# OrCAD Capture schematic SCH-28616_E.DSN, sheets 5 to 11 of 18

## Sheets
5 M-06 Audio: size C
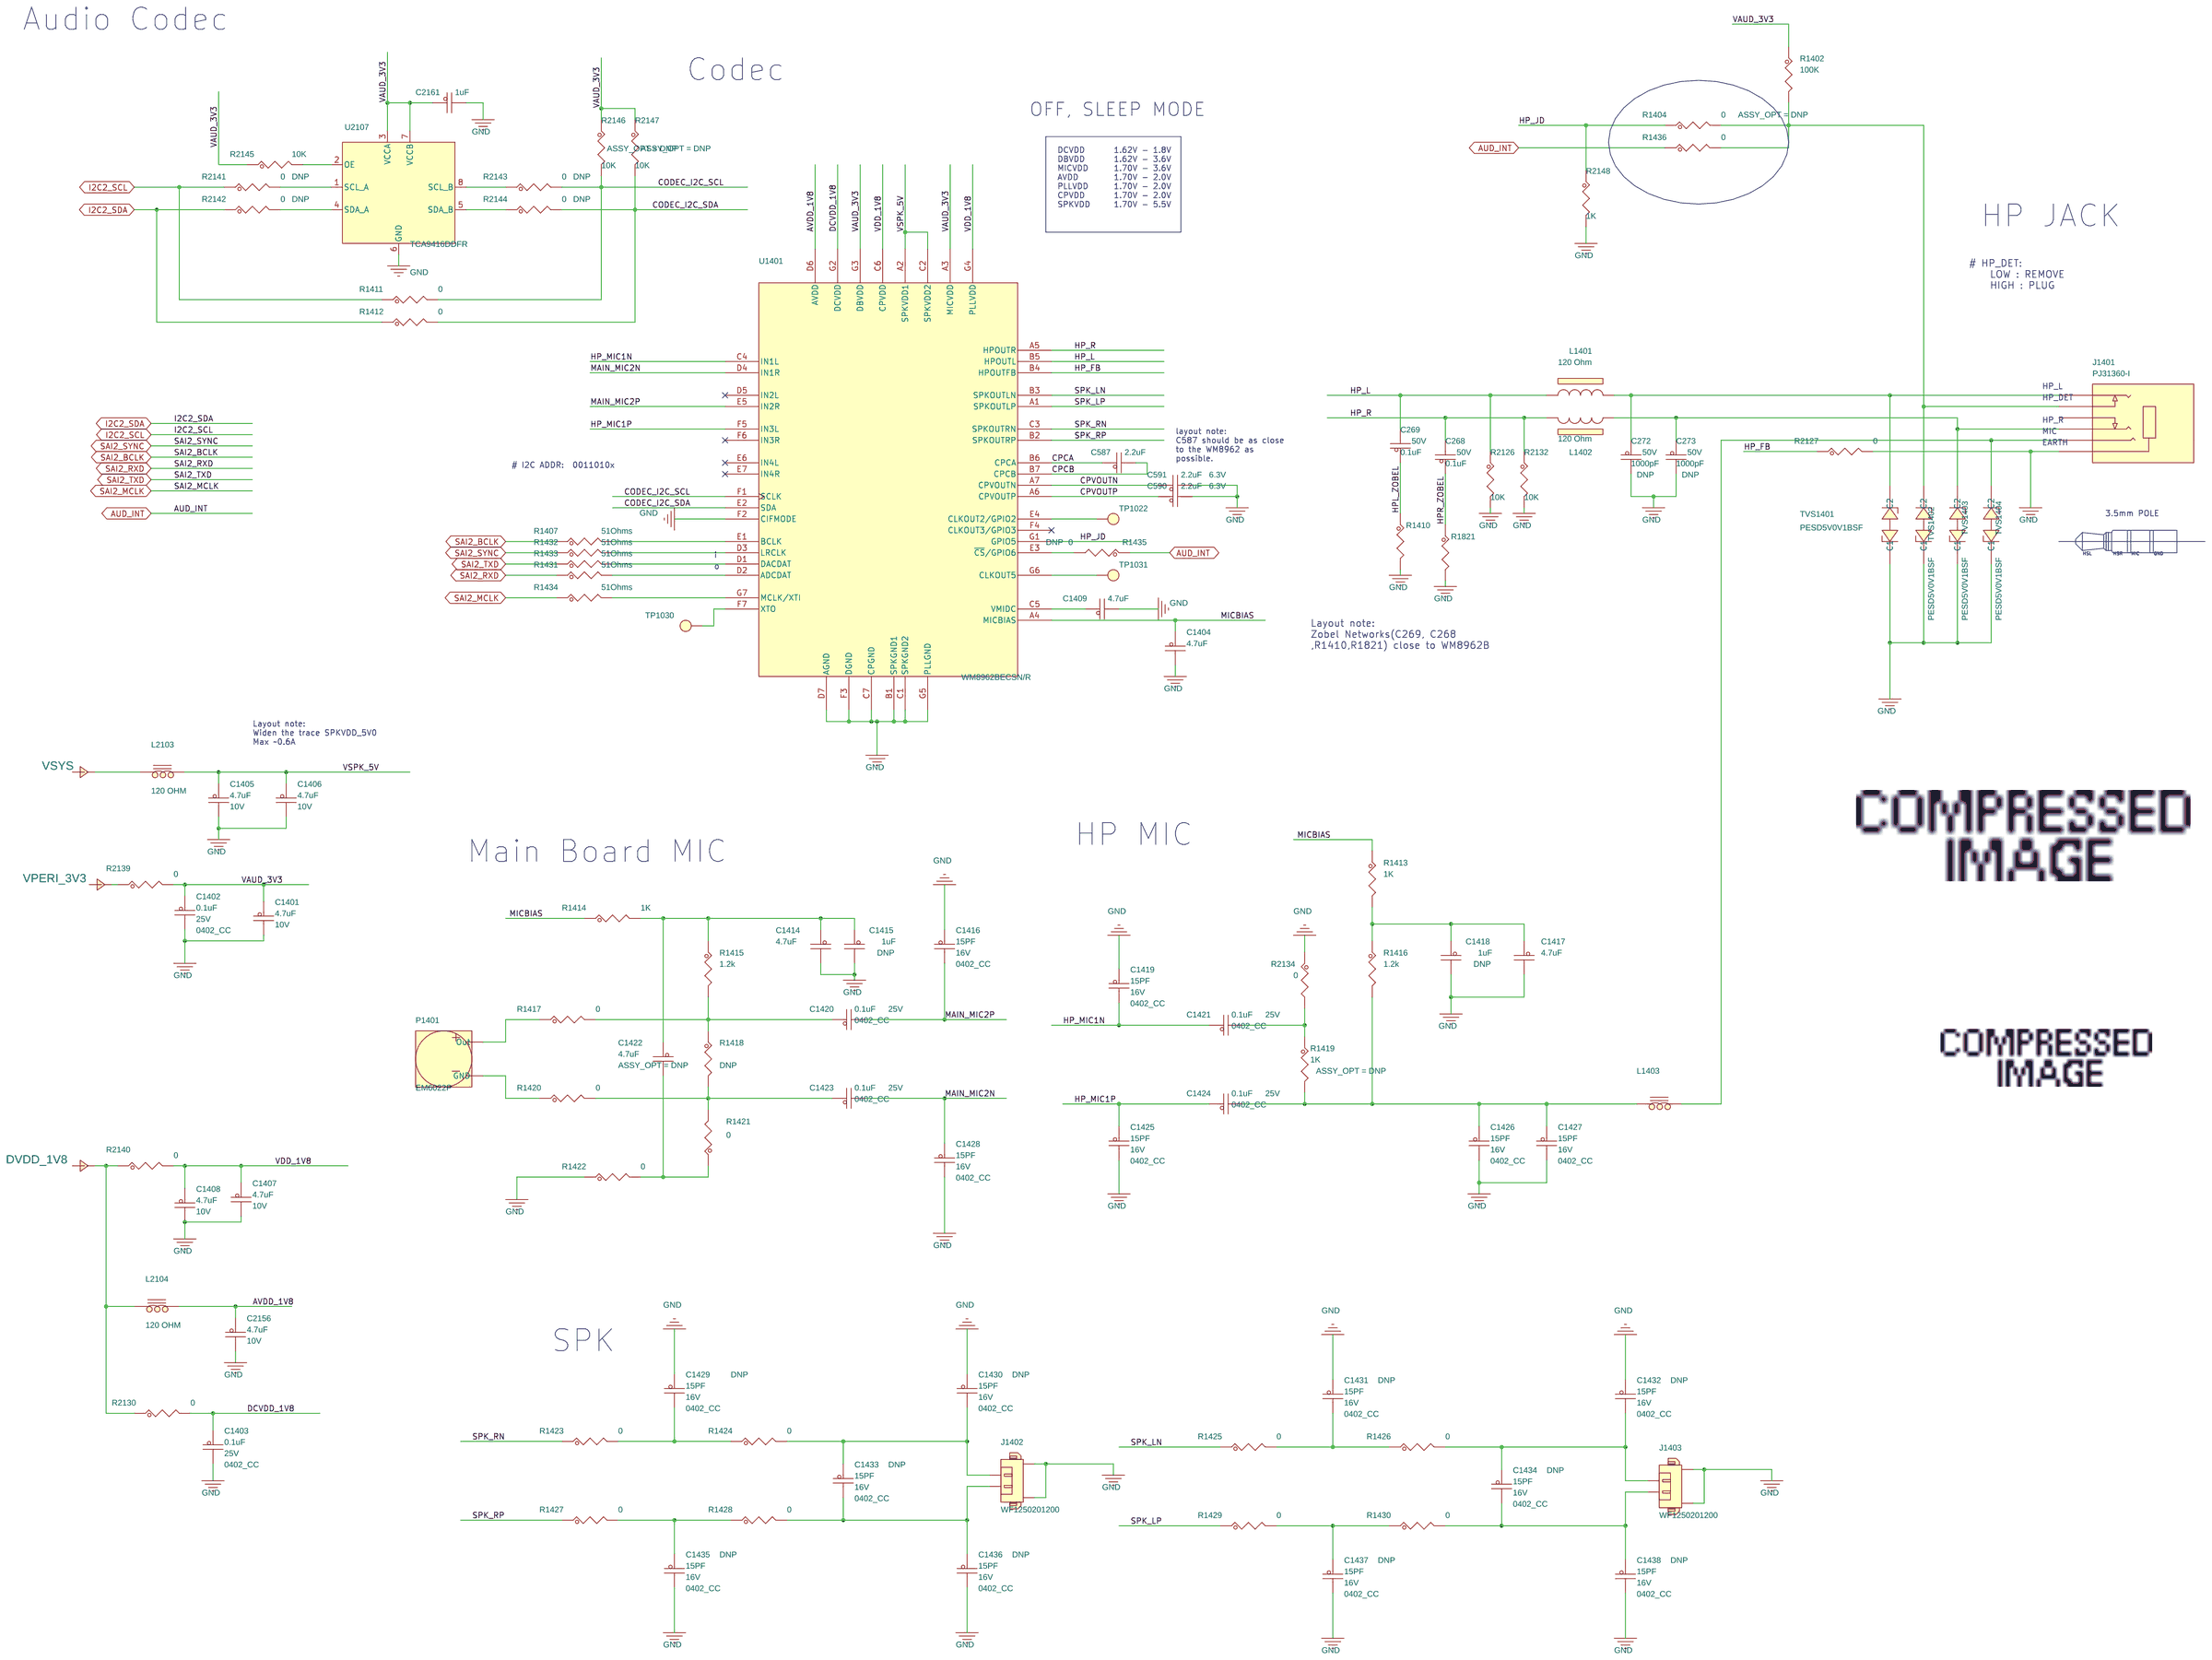
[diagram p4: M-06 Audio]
6 M-05 Sensor: size C
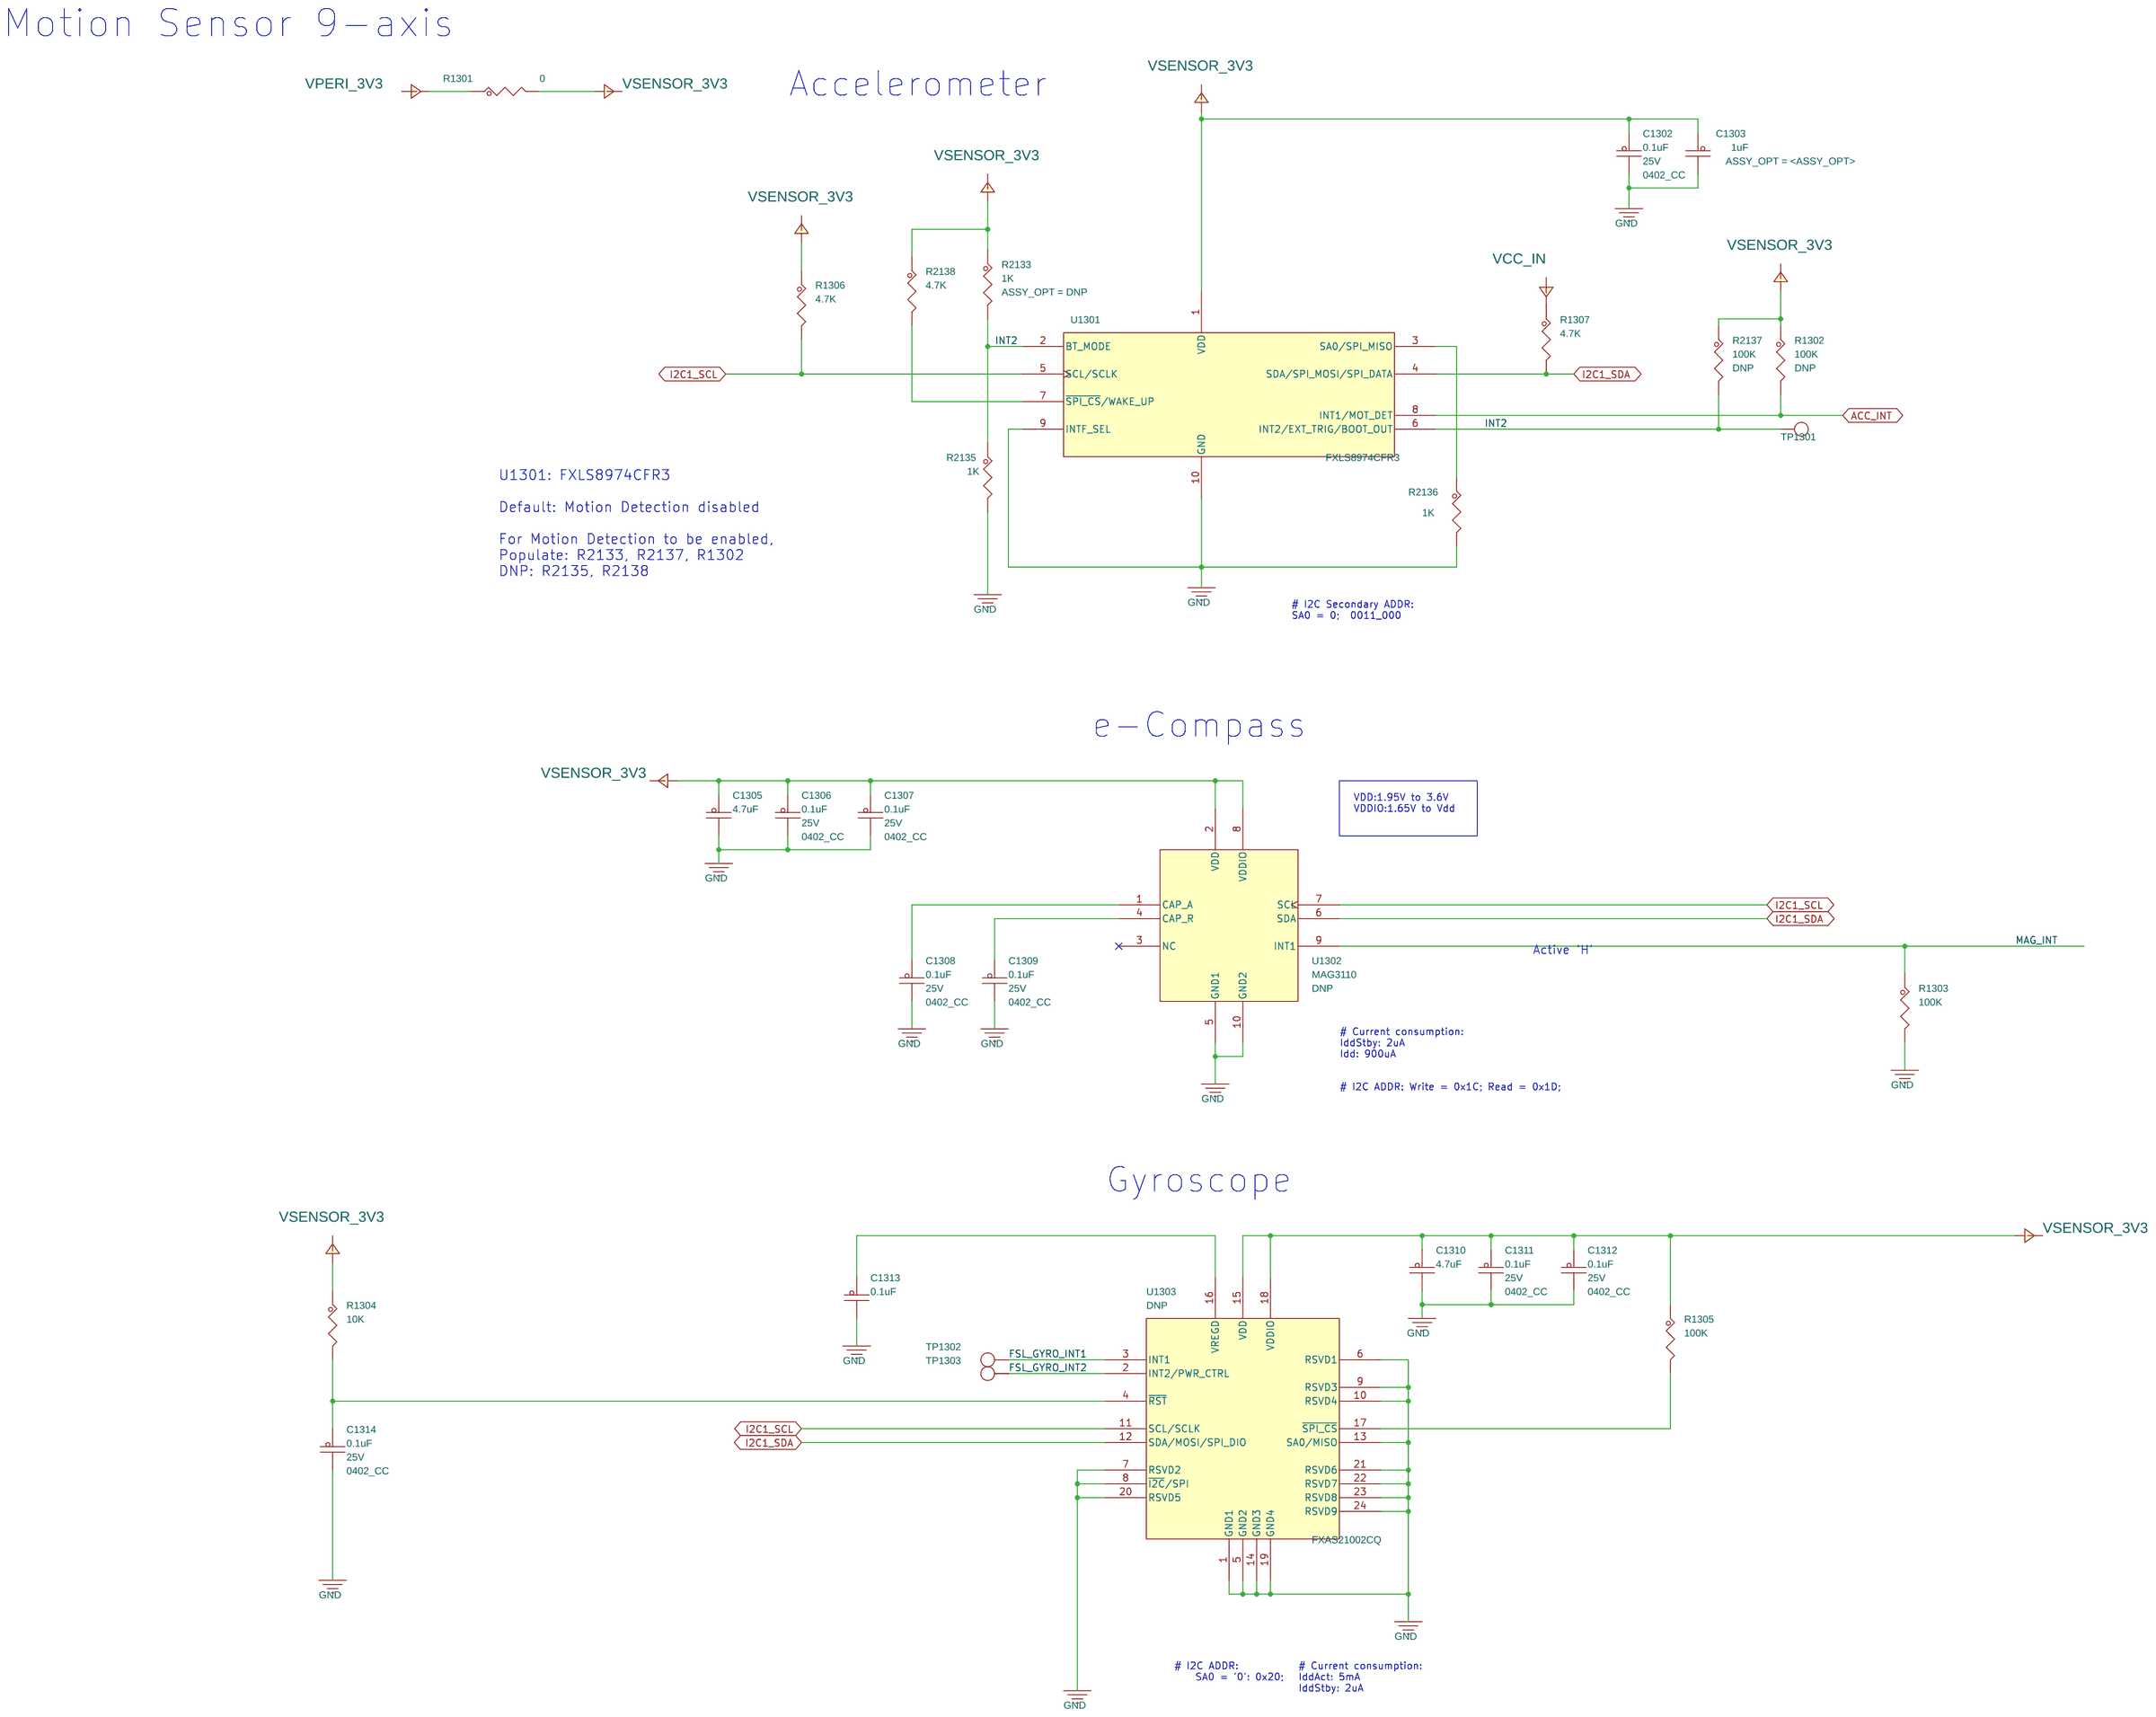
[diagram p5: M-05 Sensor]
7 M-04 CAN BUS: size C
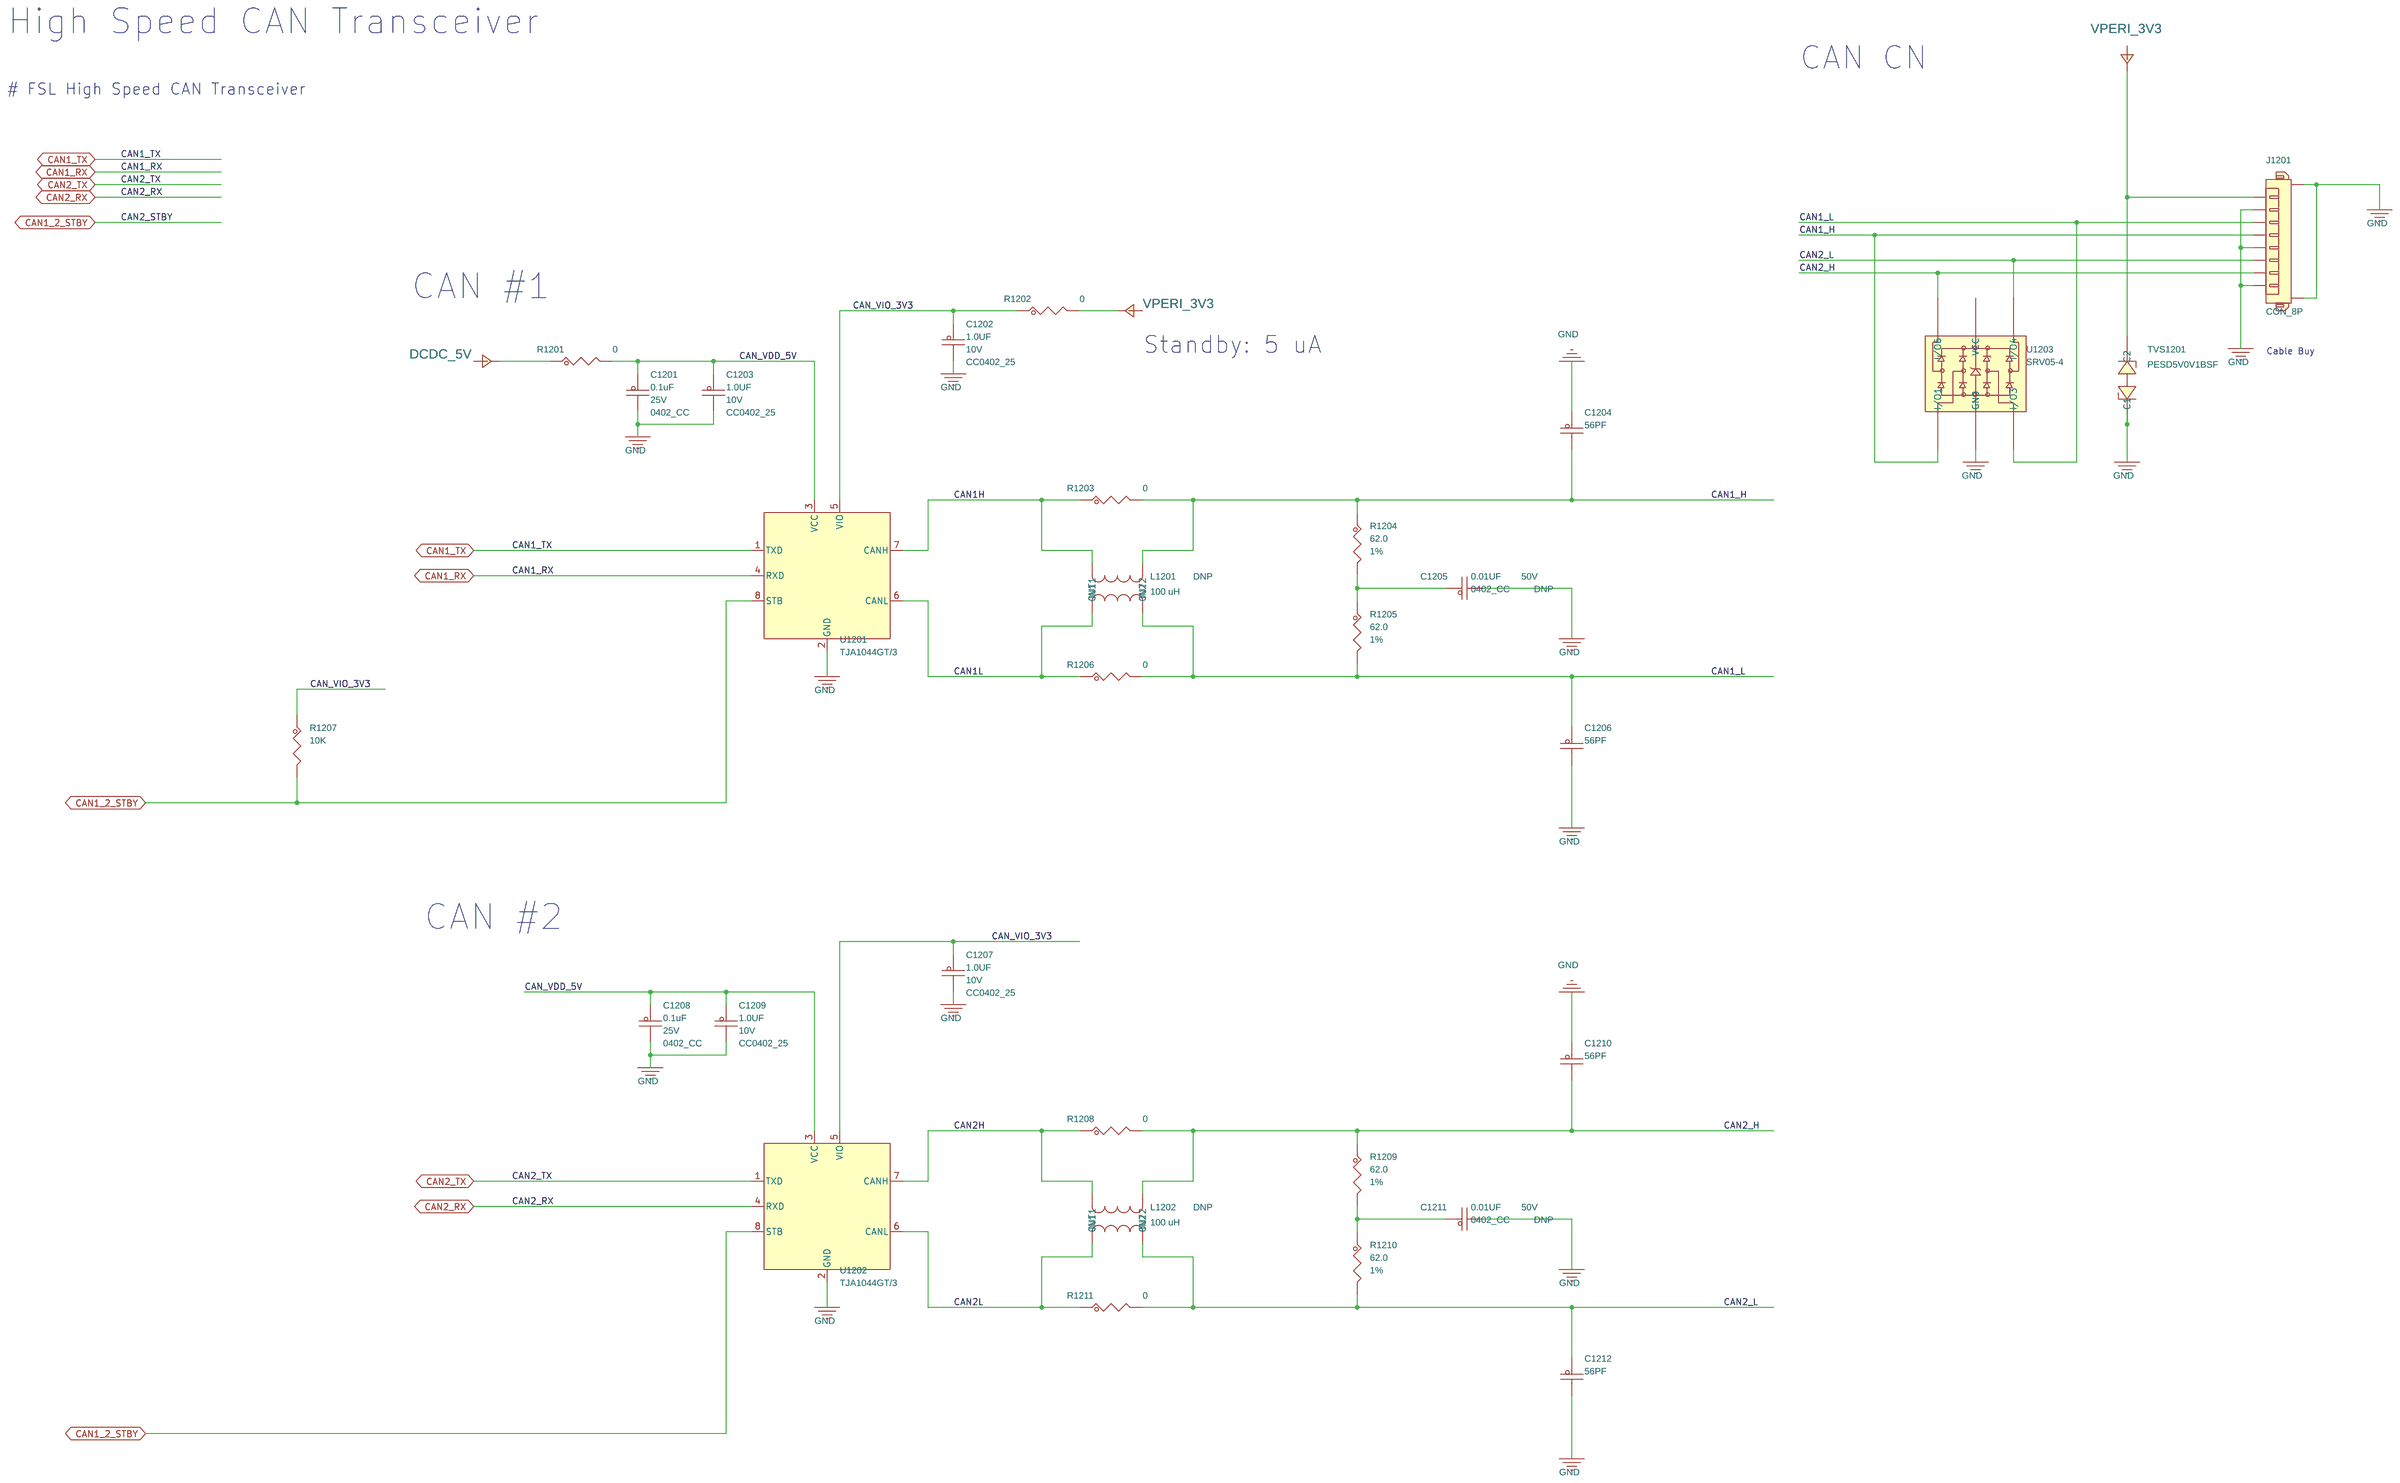
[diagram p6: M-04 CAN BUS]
8 M-01 LCD: size C
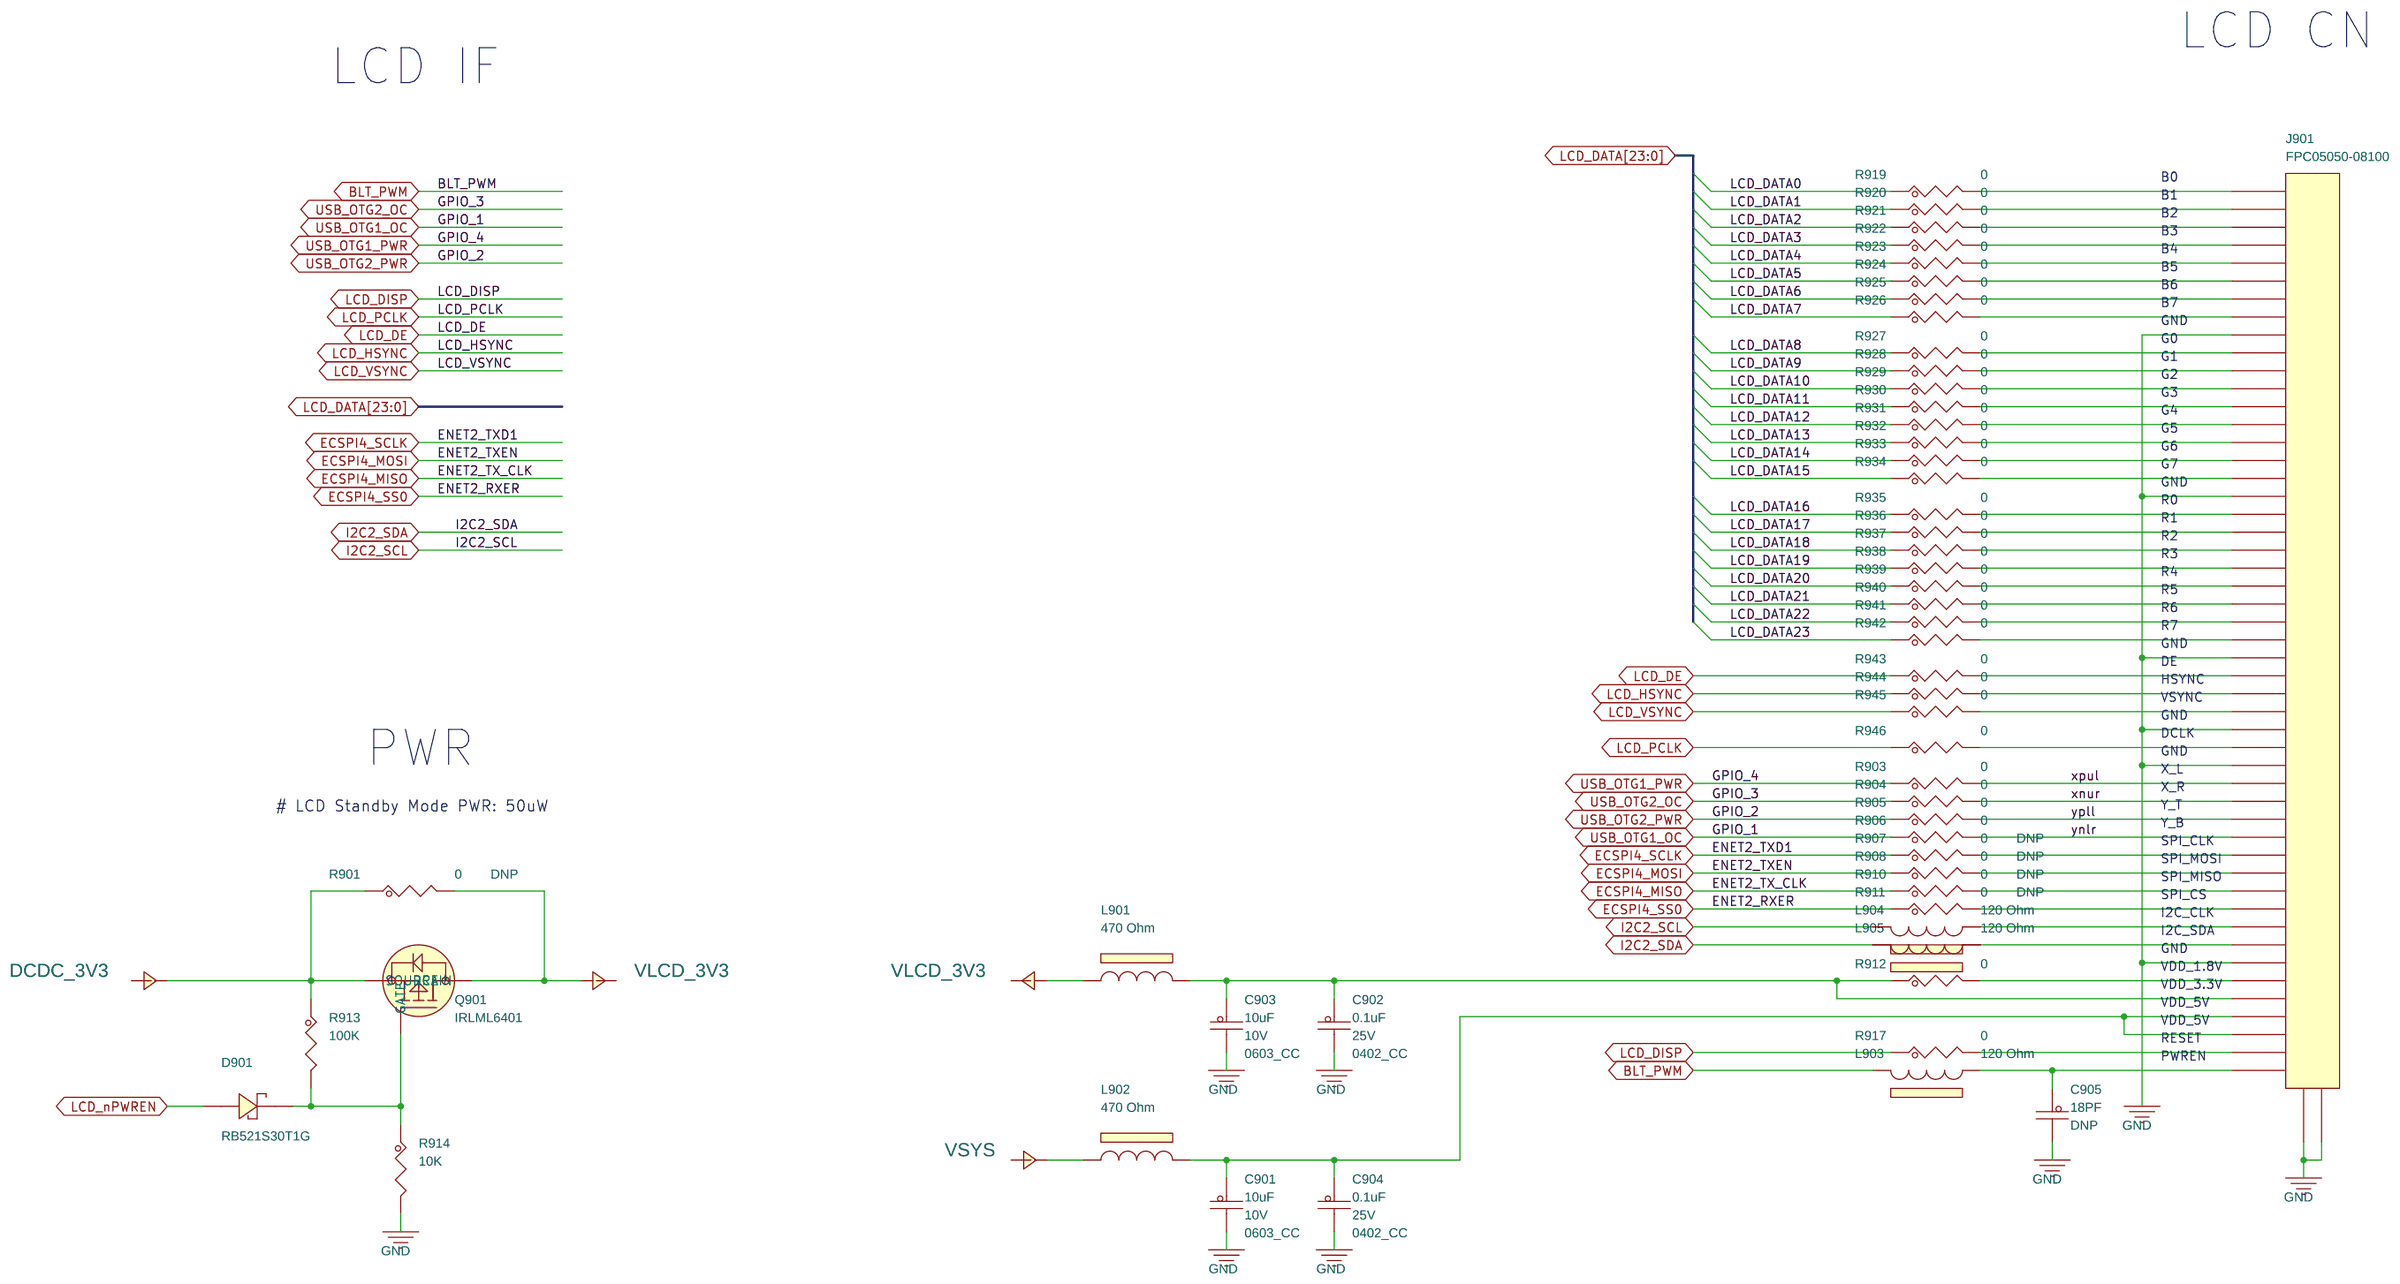
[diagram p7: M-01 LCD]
9 A-02 PWR TREE
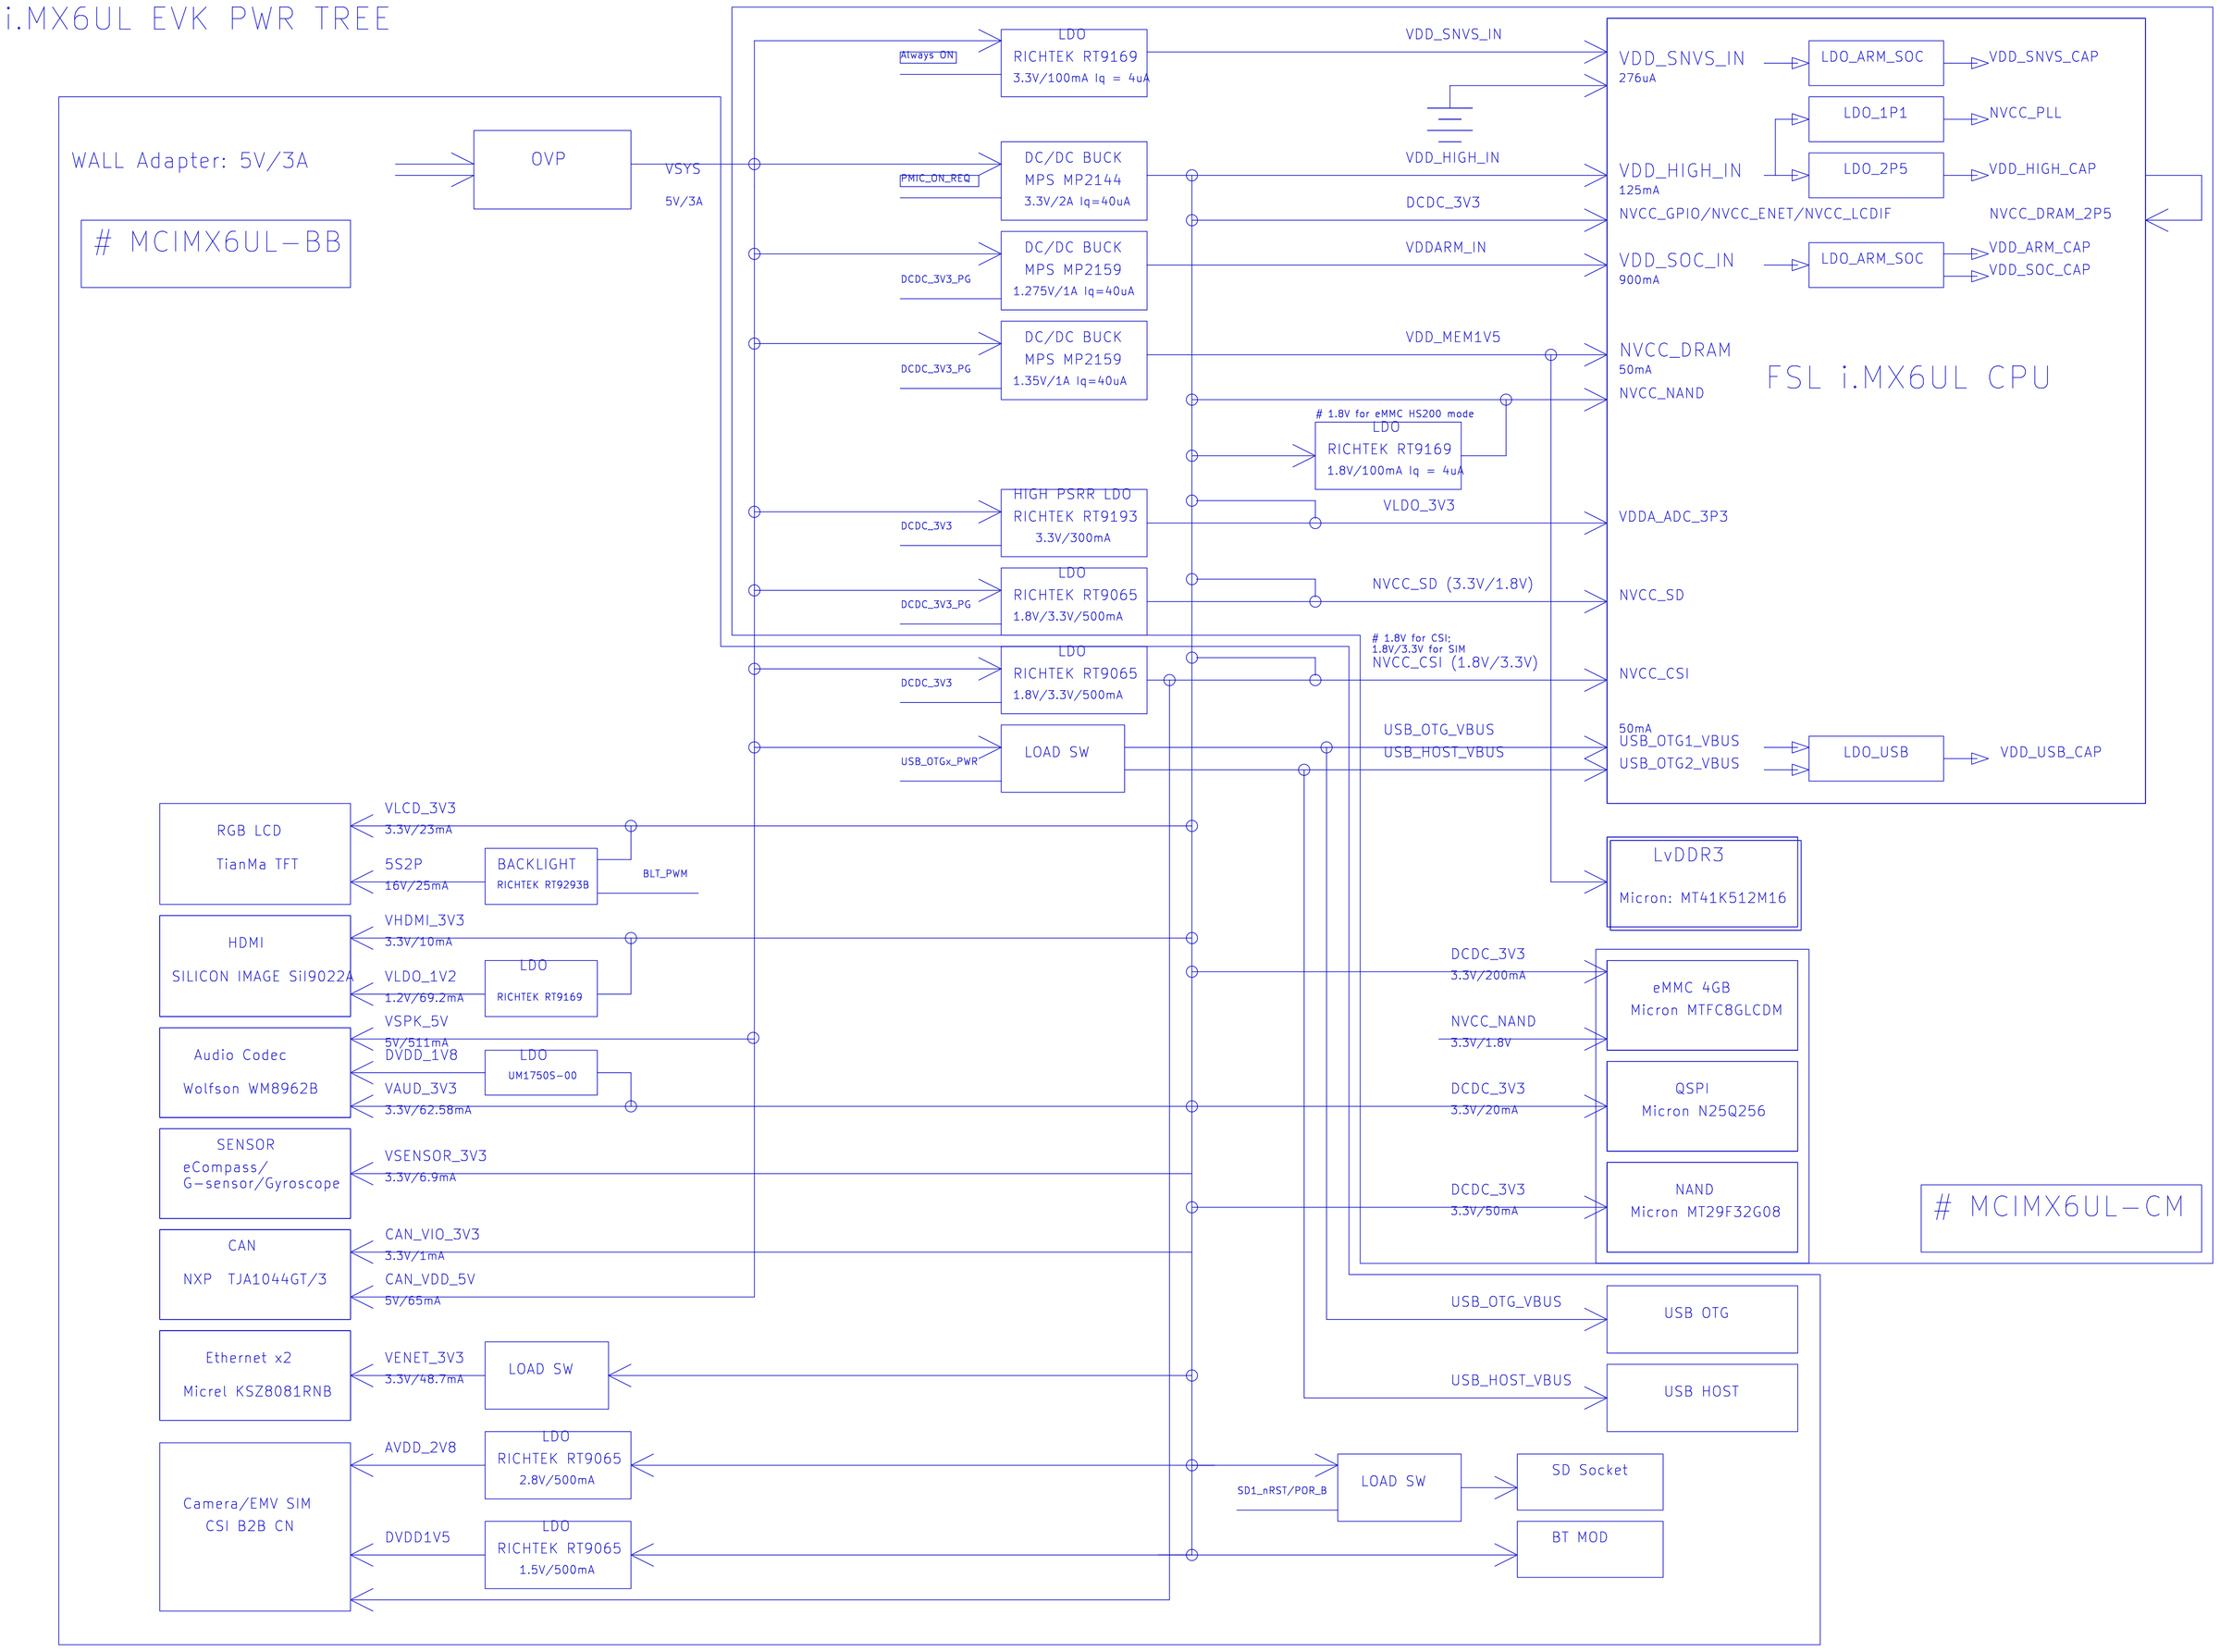
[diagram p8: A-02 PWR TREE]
10 A-01 BLOCK DIAGRAM
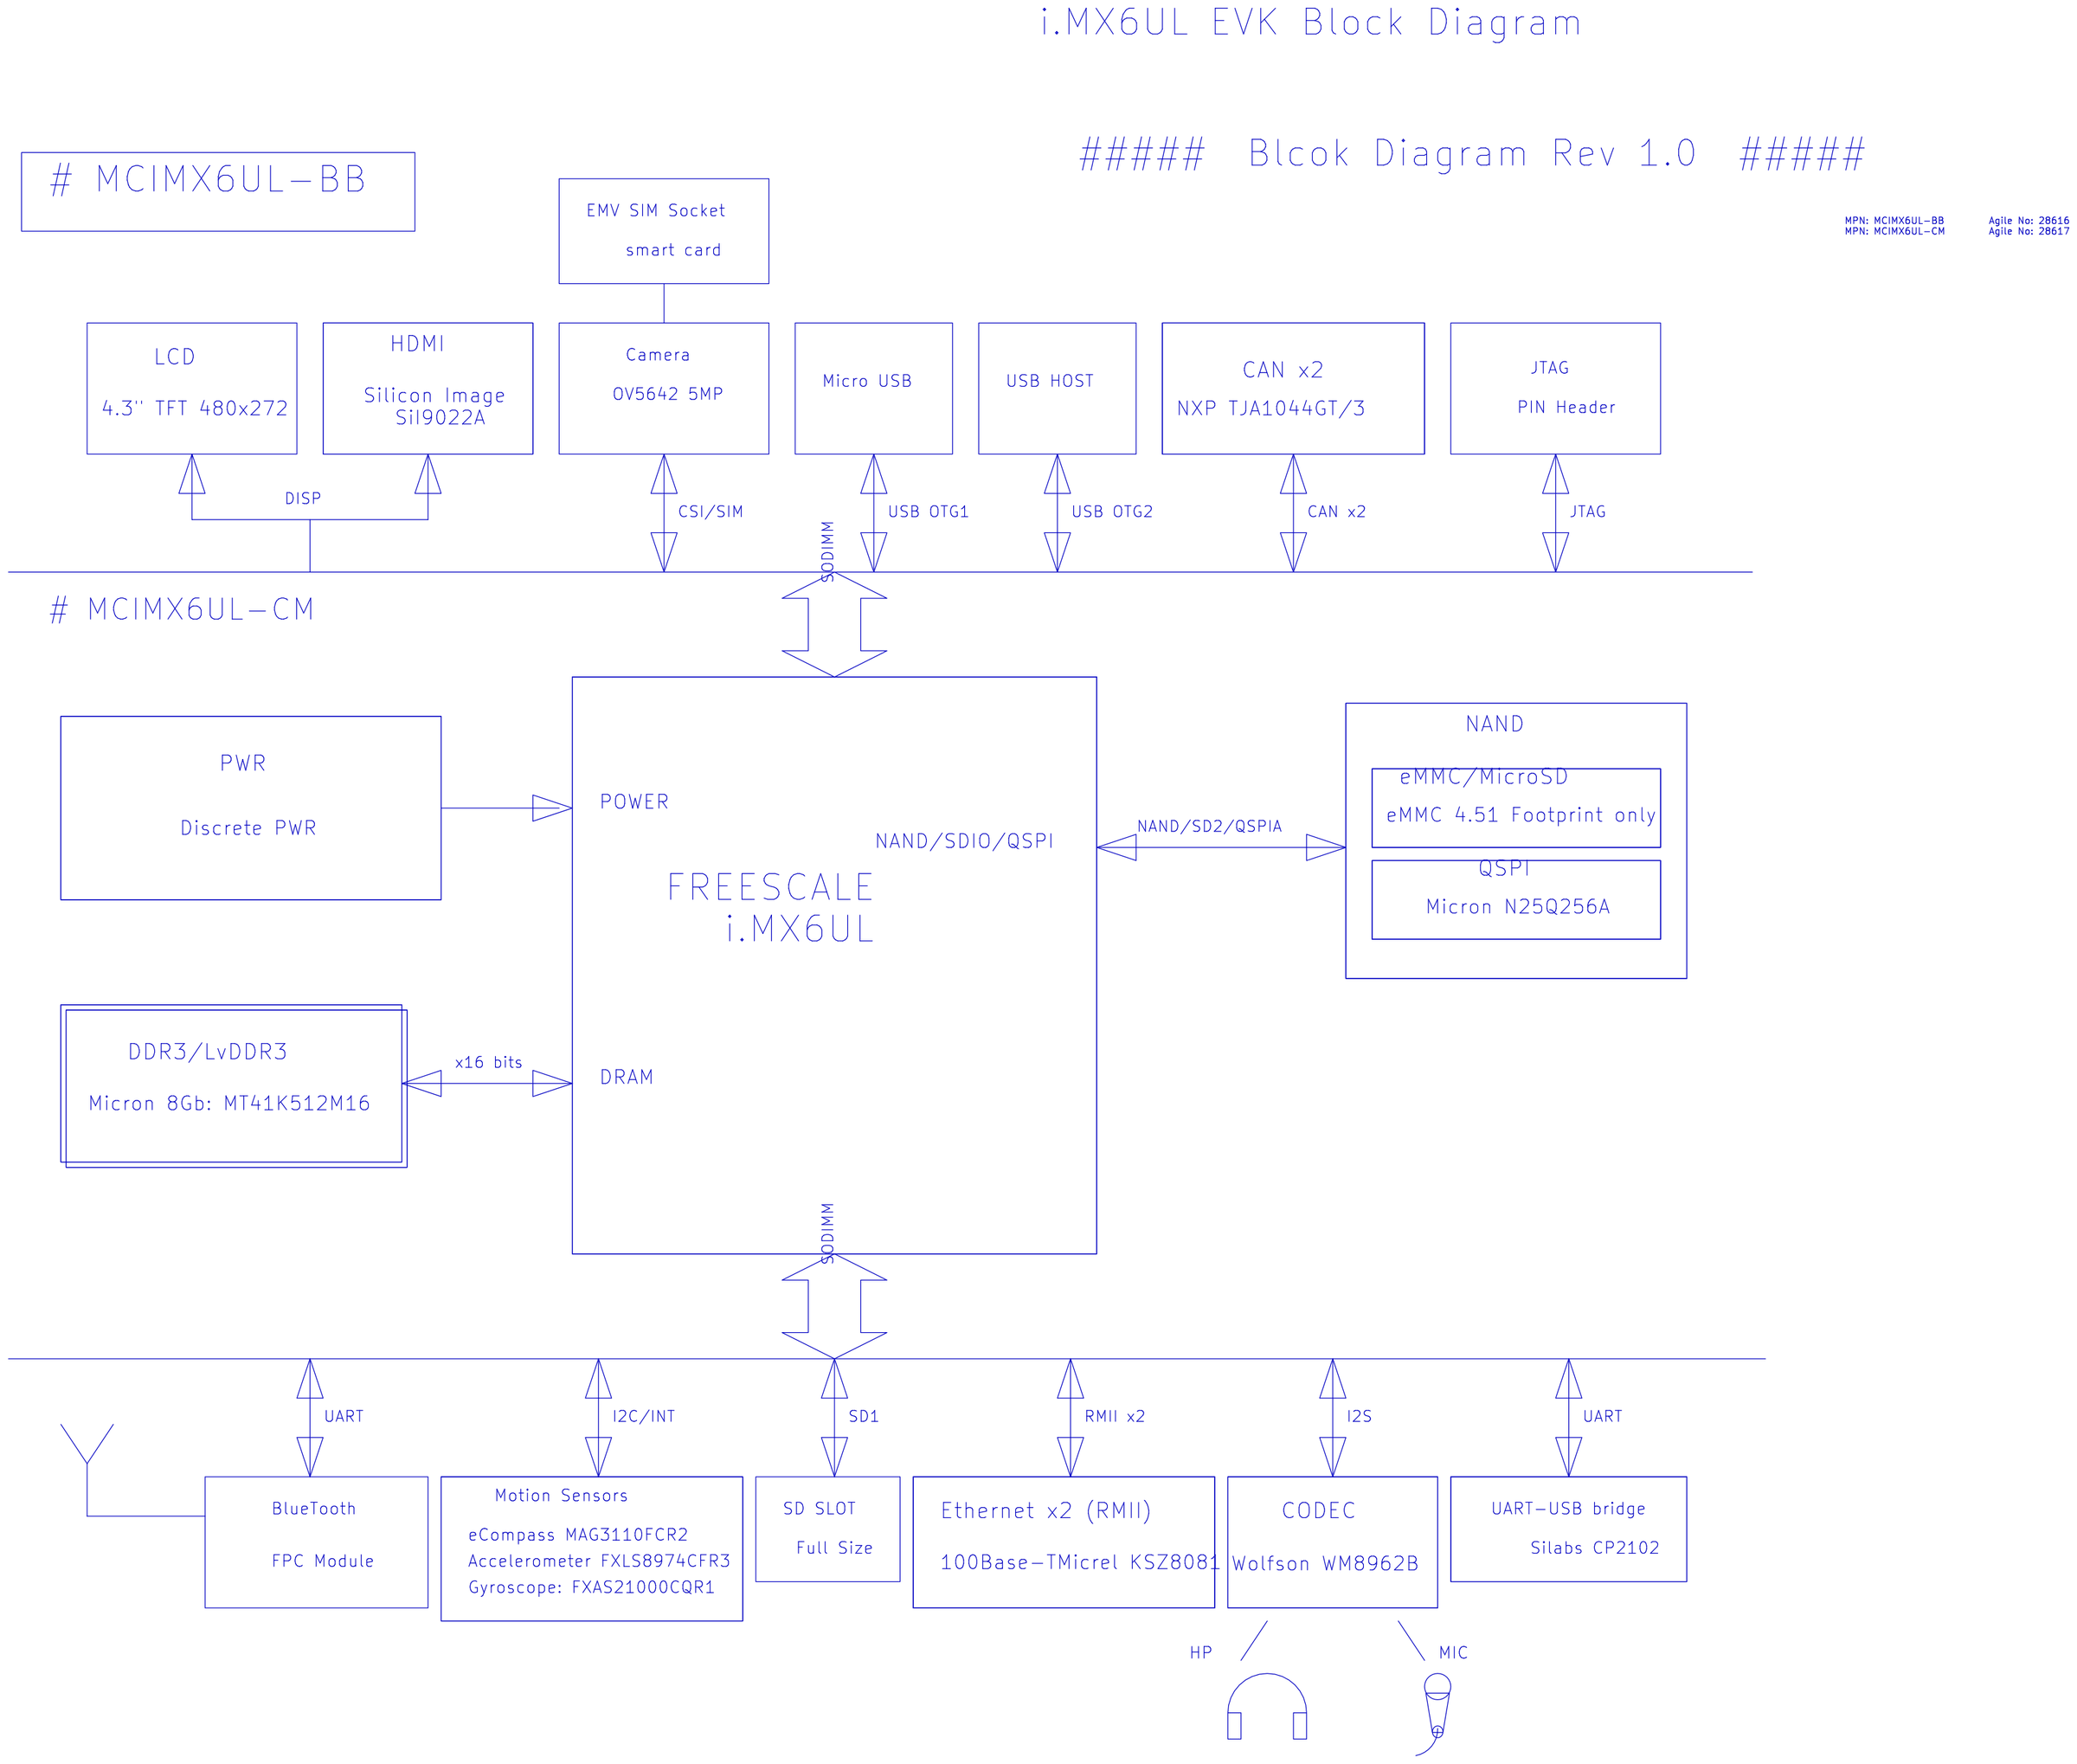
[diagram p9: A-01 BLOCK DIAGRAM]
11 A-00 COVER
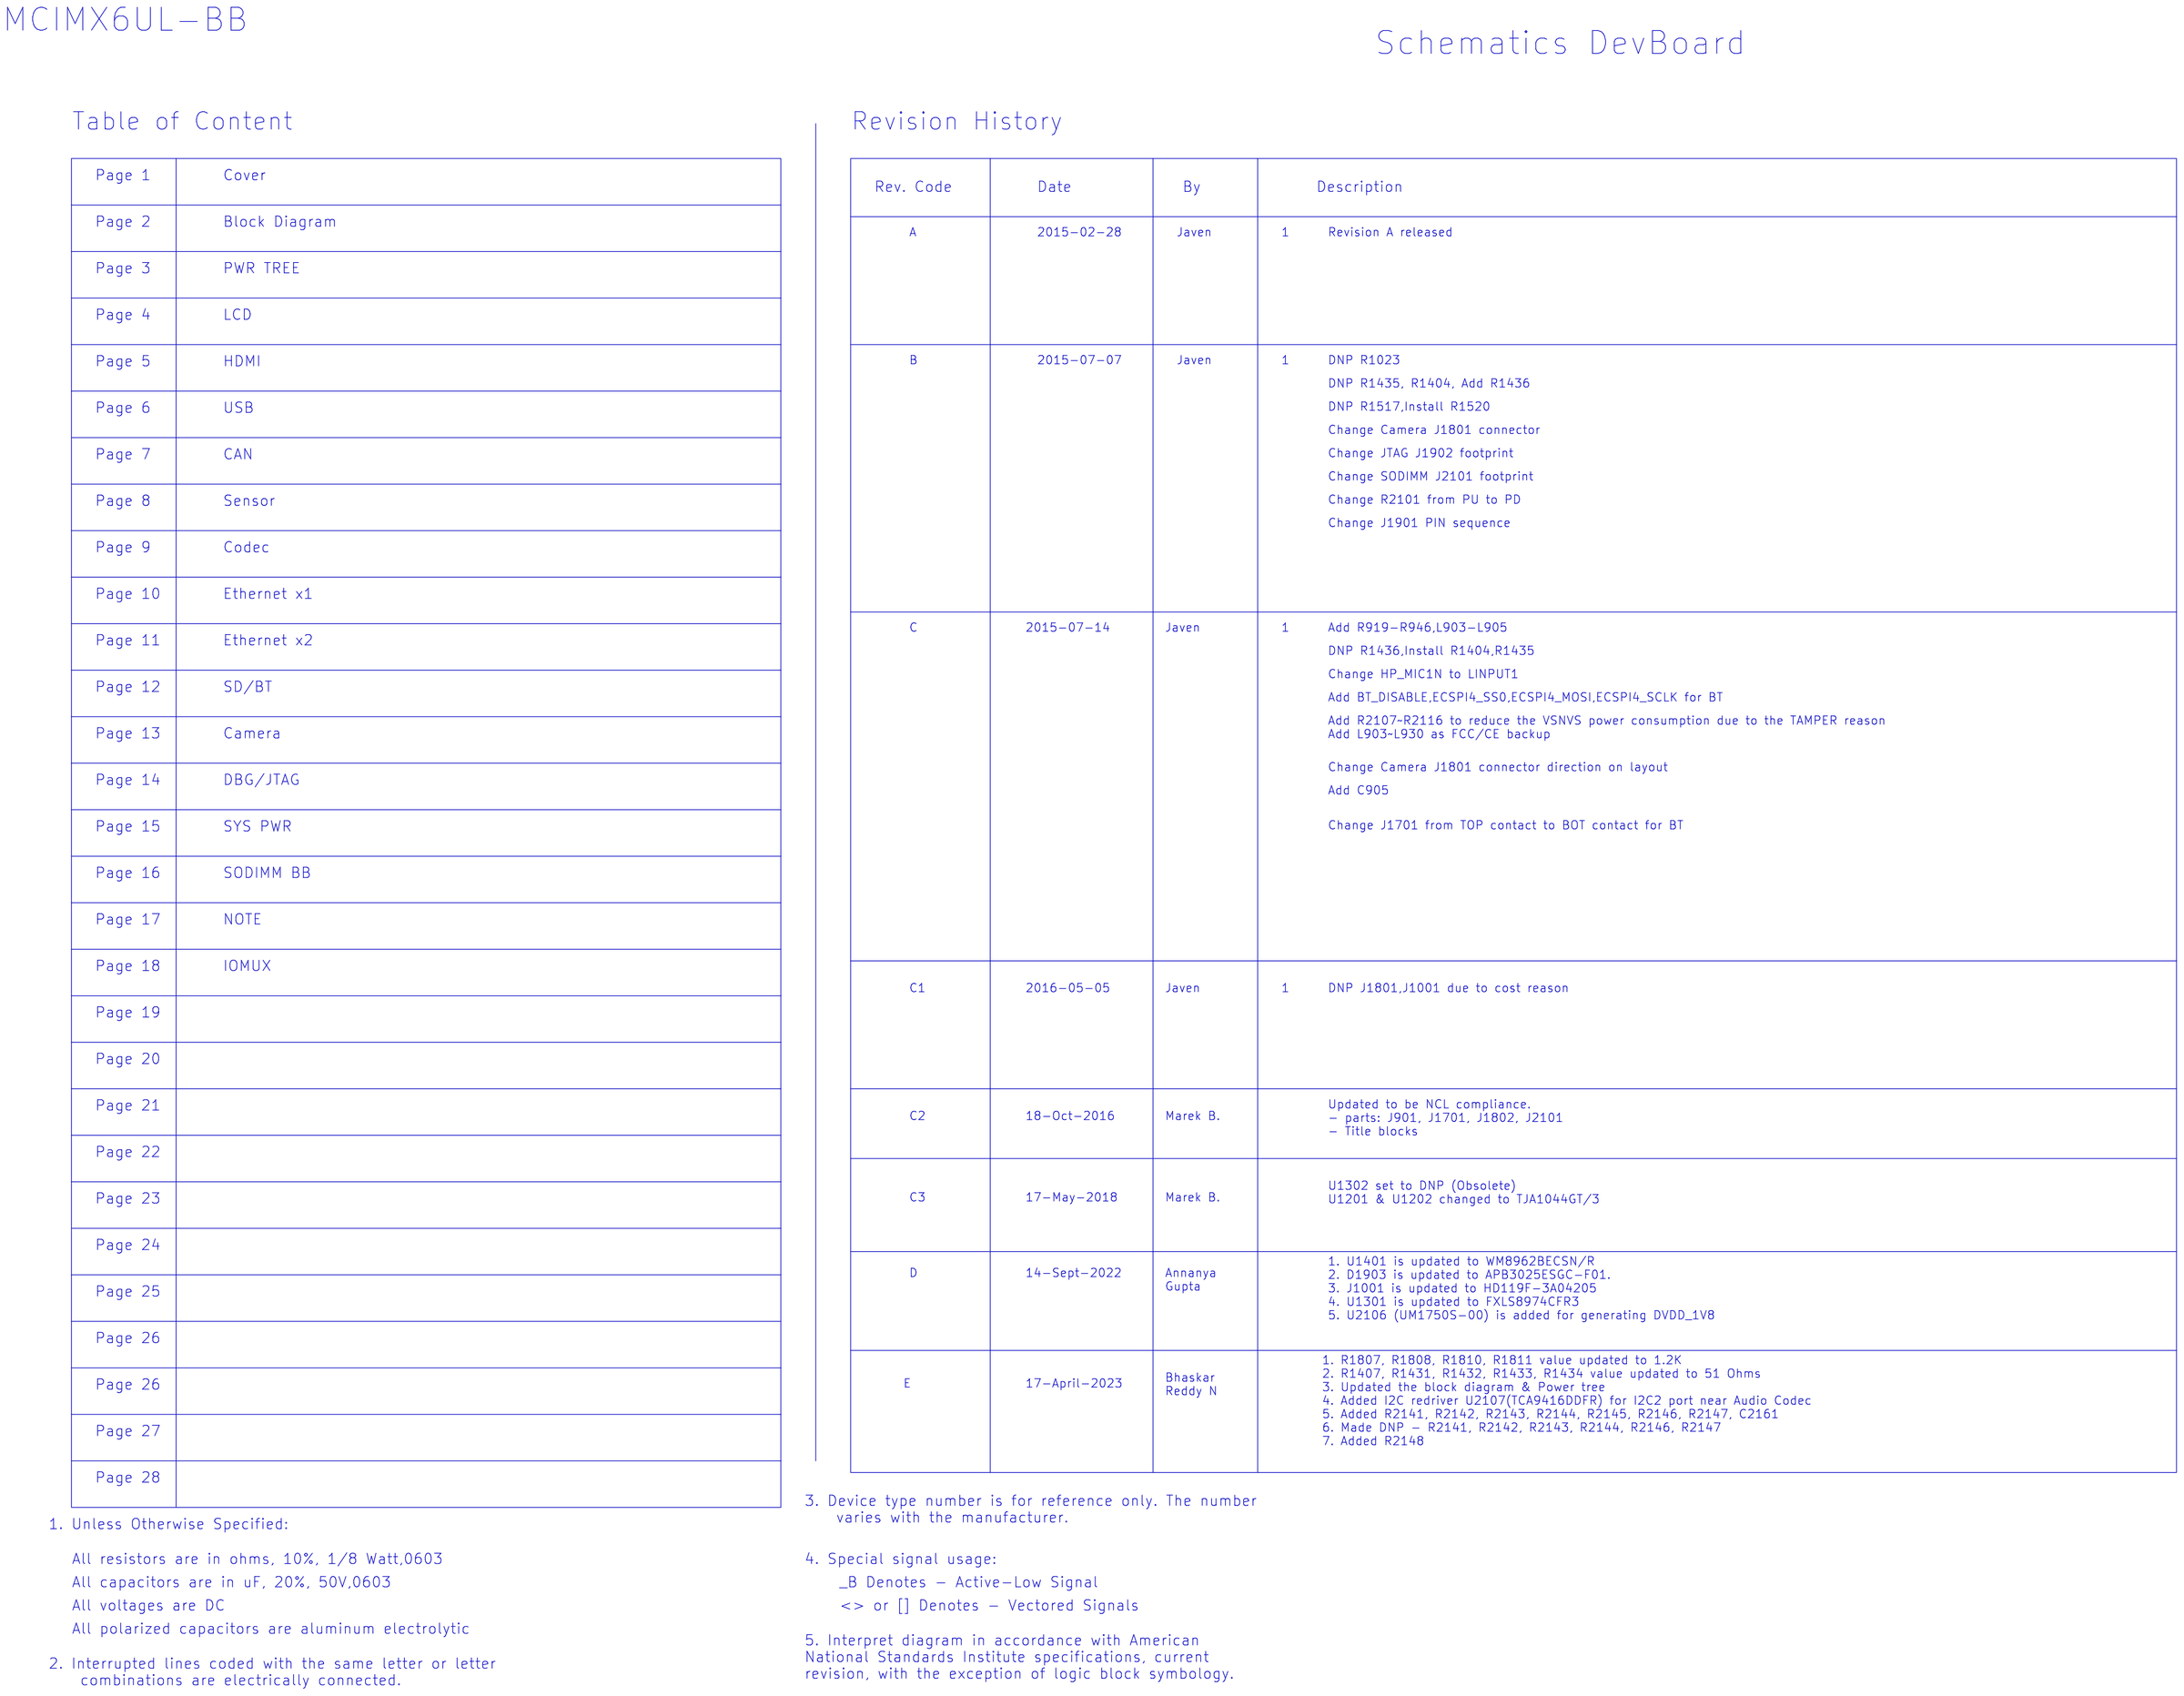
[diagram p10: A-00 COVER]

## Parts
sheet M-01 LCD
C901  10uF  [0603_CC]
C902  0.1uF  [0402_CC]
C903  10uF  [0603_CC]
C904  0.1uF  [0402_CC]
C905  18PF  [0402_CC]
D901  RB521S30T1G  [sod_523]
J901  FPC05050-08100  [con50_fpc_0p5_ra_smt_2sh]
L901  470 Ohm  [IND0603_CC]
L902  470 Ohm  [IND0603_CC]
L903  120 Ohm  [0402_CC]
L904  120 Ohm  [0402_CC]
L905  120 Ohm  [0402_CC]
Q901  IRLML6401  [sot-23]
R901  0  [0603_CC]
R903  0  [0402_CC]
R904  0  [0402_CC]
R905  0  [0402_CC]
R906  0  [0402_CC]
R907  0  [0402_CC]
R908  0  [0402_CC]
R910  0  [0402_CC]
R911  0  [0402_CC]
R912  0  [0402_CC]
R913  100K  [0402_CC]
R914  10K  [0402_CC]
R917  0  [0402_CC]
R919  0  [0402_CC]
R920  0  [0402_CC]
R921  0  [0402_CC]
R922  0  [0402_CC]
R923  0  [0402_CC]
R924  0  [0402_CC]
R925  0  [0402_CC]
R926  0  [0402_CC]
R927  0  [0402_CC]
R928  0  [0402_CC]
R929  0  [0402_CC]
R930  0  [0402_CC]
R931  0  [0402_CC]
R932  0  [0402_CC]
R933  0  [0402_CC]
R934  0  [0402_CC]
R935  0  [0402_CC]
R936  0  [0402_CC]
R937  0  [0402_CC]
R938  0  [0402_CC]
R939  0  [0402_CC]
R940  0  [0402_CC]
R941  0  [0402_CC]
R942  0  [0402_CC]
R943  0  [0402_CC]
R944  0  [0402_CC]
R945  0  [0402_CC]
R946  0  [0402_CC]
sheet M-04 CAN BUS
C1201  0.1uF  [0402_CC]
C1202  1.0UF  [CC0402_25]
C1203  1.0UF  [CC0402_25]
C1204  56PF  [CC0402_25]
C1205  0.01UF  [0402_CC]
C1206  56PF  [CC0402_25]
C1207  1.0UF  [CC0402_25]
C1208  0.1uF  [0402_CC]
C1209  1.0UF  [CC0402_25]
C1210  56PF  [CC0402_25]
C1211  0.01UF  [0402_CC]
C1212  56PF  [CC0402_25]
J1201  CON_8P  [con_w2b_8m_1p25_sm_ra]
L1201  100 uH  [ind_1812_4p]
L1202  100 uH  [ind_1812_4p]
R1201  0  [0402_CC]
R1202  0  [0402_CC]
R1203  0  [0402_CC]
R1204  62.0  [0805_CC]
R1205  62.0  [0805_CC]
R1206  0  [0402_CC]
R1207  10K  [0402_CC]
R1208  0  [0402_CC]
R1209  62.0  [0805_CC]
R1210  62.0  [0805_CC]
R1211  0  [0402_CC]
TVS1201  PESD5V0V1BSF  [dsn0603-2]
U1201  TJA1044GT/3  [SO8_1P27_4X5]
U1202  TJA1044GT/3  [SO8_1P27_4X5]
U1203  SRV05-4  [SOT23_S6]
sheet M-05 Sensor
C1302  0.1uF  [0402_CC]
C1303  1uF  [0402_CC]
C1305  4.7uF  [cc0402_tol0p15]
C1306  0.1uF  [0402_CC]
C1307  0.1uF  [0402_CC]
C1308  0.1uF  [0402_CC]
C1309  0.1uF  [0402_CC]
C1310  4.7uF  [cc0402_tol0p15]
C1311  0.1uF  [0402_CC]
C1312  0.1uF  [0402_CC]
C1313  0.1uF  [0402_CC]
C1314  0.1uF  [0402_CC]
R1301  0  [0402_CC]
R1302  100K  [0402_CC]
R1303  100K  [0402_CC]
R1304  10K  [0402_CC]
R1305  100K  [0402_CC]
R1306  4.7K  [0402_CC]
R1307  4.7K  [0402_CC]
R2133  1K  [0402_CC]
R2135  1K  [0402_CC]
R2136  1K  [0402_CC]
R2137  100K  [0402_CC]
R2138  4.7K  [0402_CC]
TP1301  TPAD_020  [tpad_020]
TP1302  TPAD_020  [tpad_020]
TP1303  TPAD_020  [tpad_020]
U1301  FXLS8974CFR3  [DFN_10_0P4_2X2]
U1302  MAG3110  [DFN_10_0P4_2X2_B]
U1303  FXAS21002CQ  [QFN24_0P5_4X4_ASYM_EXP]
sheet M-06 Audio
C268  0.1uF  [CC0402_25]
C269  0.1uF  [CC0402_25]
C272  1000pF  [CC0402_25]
C273  1000pF  [CC0402_25]
C587  2.2uF  [0402_CC]
C590  2.2uF  [0402_CC]
C591  2.2uF  [0402_CC]
C1401  4.7uF  [0603_CC]
C1402  0.1uF  [0402_CC]
C1403  0.1uF  [0402_CC]
C1404  4.7uF  [cc0402_tol0p15]
C1405  4.7uF  [0603_CC]
C1406  4.7uF  [0603_CC]
C1407  4.7uF  [0603_CC]
C1408  4.7uF  [0603_CC]
C1409  4.7uF  [cc0402_tol0p15]
C1414  4.7uF  [cc0402_tol0p15]
C1415  1uF  [0402_CC]
C1416  15PF  [0402_CC]
C1417  4.7uF  [cc0402_tol0p15]
C1418  1uF  [0402_CC]
C1419  15PF  [0402_CC]
C1420  0.1uF  [0402_CC]
C1421  0.1uF  [0402_CC]
C1422  4.7uF  [cc0402_tol0p15]
C1423  0.1uF  [0402_CC]
C1424  0.1uF  [0402_CC]
C1425  15PF  [0402_CC]
C1426  15PF  [0402_CC]
C1427  15PF  [0402_CC]
C1428  15PF  [0402_CC]
C1429  15PF  [0402_CC]
C1430  15PF  [0402_CC]
C1431  15PF  [0402_CC]
C1432  15PF  [0402_CC]
C1433  15PF  [0402_CC]
C1434  15PF  [0402_CC]
C1435  15PF  [0402_CC]
C1436  15PF  [0402_CC]
C1437  15PF  [0402_CC]
C1438  15PF  [0402_CC]
C2156  4.7uF  [0603_CC]
C2161  1uF  [0402_CC]
J1401  PJ31360-I  [con6_audjack_ra_th]
J1402  WF1250201200  [con1x2_1p25_sm]
J1403  WF1250201200  [con1x2_1p25_sm]
L1401  120 Ohm  [0402_CC]
L1402  120 Ohm  [0402_CC]
L1403  120OHM  [0603_CC]
L2103  120 OHM  [IND_0603]
L2104  120 OHM  [IND_0603]
P1401  EM6022P  [mic_WM-63PR]
R1402  100K  [0402_CC]
R1404  0  [0402_CC]
R1407  51Ohms  [RC0402_25]
R1410  20  [0603_CC]
R1411  0  [0402_CC]
R1412  0  [0402_CC]
R1413  1K  [0402_CC]
R1414  1K  [0402_CC]
R1415  1.2k  [0402_CC]
R1416  1.2k  [0402_CC]
R1417  0  [0402_CC]
R1418  10K  [0402_CC]
R1419  1K  [0402_CC]
R1420  0  [0402_CC]
R1421  0  [0402_CC]
R1422  0  [0402_CC]
R1423  0  [0402_CC]
R1424  0  [0402_CC]
R1425  0  [0402_CC]
R1426  0  [0402_CC]
R1427  0  [0402_CC]
R1428  0  [0402_CC]
R1429  0  [0402_CC]
R1430  0  [0402_CC]
R1431  51Ohms  [RC0402_25]
R1432  51Ohms  [RC0402_25]
R1433  51Ohms  [RC0402_25]
R1434  51Ohms  [RC0402_25]
R1435  0  [0402_CC]
R1436  0  [0402_CC]
R1821  20  [0603_CC]
R2126  10K  [RC0402_25]
R2127  0  [0402_CC]
R2130  0  [0402_CC]
R2132  10K  [RC0402_25]
R2134  0  [0402_CC]
R2139  0  [0402_CC]
R2140  0  [0402_CC]
R2141  0  [0402_CC]
R2142  0  [0402_CC]
R2143  0  [0402_CC]
R2144  0  [0402_CC]
R2145  10K  [RC0402_25]
R2146  10K  [RC0402_25]
R2147  10K  [RC0402_25]
R2148  1K  [0402_CC]
TP1022  TP_35MIL  [testpoint_35mil]
TP1030  TP_35MIL  [testpoint_35mil]
TP1031  TP_35MIL  [testpoint_35mil]
TVS1401  PESD5V0V1BSF  [dsn0603-2]
TVS1402  PESD5V0V1BSF  [dsn0603-2]
TVS1403  PESD5V0V1BSF  [dsn0603-2]
TVS1404  PESD5V0V1BSF  [dsn0603-2]
U1401  WM8962BECSN/R  [BGA49_0P5_3P62X4]
U2107  TCA9416DDFR  [sot-23-8-thin]

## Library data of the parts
C901 C903 = CAP_NP: CAP CER 10UF 10V 20% X5R 0603; AGILE_PN: 150-78609; CAD_APPROVED: Yes; FPLIST: CC0603_OV,CC0603,0603_CC; HEIGHT: 1.016MM; MFG_NAME01: TAIYO YUDEN; MFG_PN01: LMK107BJ106MALTD; Package Size: 0603; Package Type: Paper Tape; ROHS: Yes; Rated Voltage: 10V; Temp Range: -55C to +85C; Tolerance: 20%; VOLTAGE: 10V
C902 C904 C1201 C1208 C1302 C1306-C1309 C1311-C1314 C1402 C1403 C1420 C1421 C1423 C1424 = CAP_NP: CAP CER 0.1UF 25V 10% X5R 0402; AGILE_PN: 150-78633; CAD_APPROVED: Yes; FPLIST: CC0402_25,CC0402_HD,0402_CC; HEIGHT: 0.55MM; MFG_NAME01: YAGEO AMERICA; MFG_PN01: CC0402KRX5R8BB104; Package Size: 0402; ROHS: Yes; Rated Voltage: 25V; Temp Range: -55C to +85C; Tolerance: 10%; VOLTAGE: 25V
C905 = CAP_NP: CAP CER 18PF 50V 1% C0G 0402; AGILE_PN: 150-76630; ASSY_OPT: DNP; CAD_APPROVED: Yes; FPLIST: CC0402_25,CC0402_HD,0402_CC; HEIGHT: 0.59MM; MFG_NAME01: YAGEO; MFG_PN01: CC0402FRNPO9BN180; PRIORITY_PN: 021-00248; ROHS: Yes; ROOM: ATLAS-AP; Rated Voltage: 50V; Temp Range: -55C to +125C; Tolerance: 1%; VOLTAGE: 50V
D901 = DIODE_SCHTKY: DIODE SCH 200MA 30V AEC-Q101 SOD-523; 3D_Mechanical_Footprint_File: http://fcl.am.freescale.net/ALLEGRO/step/sod_523.STEP; AGILE_PN: 480-78501; CAD_APPROVED: Yes; HEIGHT: 0.7MM; MFG_NAME01: ON SEMICONDUCTOR; ROHS: Yes; Rated Voltage: 30V
J901 = CONN_1X50_2SH: CON 1X50 FPC/FFC RA SKT SMT 0.5MM SP 87H SN/AU; AGILE_PN: 211-79710; CAD_APPROVED: Yes; FPLIST: con50_fpc_0p5_ra_smt,con50_fpc_0p5_ra_smt_2sh; HEIGHT: 2.2MM; MFG_NAME01: SHENZHEN ATOM TECHNOLOGY CO.,LTD; ROHS: Yes
L901 L902 = INDUCTOR_FERRITE: IND FER BEAD 470 OHM@100MHZ 1A 25% 0603; AGILE_PN: 180-77776; CAD_APPROVED: Yes; FPLIST: IND_0603,IND0603_CC; HEIGHT: 0.95MM; MFG_NAME01: murata; MFG_PN01: BLM18PG471SN1D; PART_TYPE: FERRITE\BEAD; ROHS: Yes; Tolerance: 25%
L903-L905 L1401 L1402 = INDUCTOR_FERRITE: IND FER BEAD 120 OHM@100MHZ 0.5A 25% 0402; AGILE_PN: 180-77771; CAD_APPROVED: Yes; FPLIST: IND_0402,0402_CC; HEIGHT: 0.55MM; MFG_NAME01: MURATA; MFG_PN01: BLM15AG121SN1D; PART_TYPE: FERRITE\BEAD; Package Size: 0402; ROHS: Yes; Tolerance: 25%
Q901 = MOSFET_P: TRAN PMOS PWR 12V 4.3A SOT23; AGILE_PN: 480-77718; CAD_APPROVED: Yes; HEIGHT: 1.12MM; MFG_NAME01: INTERNATIONAL RECTIFIER; MFG_PN01: IRLML6401TRPBF; ROHS: Yes
R901 = RES: RES MF ZERO OHM 1/10W -- 0603; AGILE_PN: 470-80866; ASSY_OPT: DNP; CAD_APPROVED: Yes; FPLIST: RC0603_OV,RC0603,R603-X2,0603_CC; HEIGHT: 0.6MM; MFG_NAME01: YAGEO AMERICA; MFG_PN01: RC0603FR-070RL; ROHS: Yes; Temp Range: –55 °C to +155 °C
R903-R906 R912 R917 R919-R946 R1201-R1203 R1206 R1208 R1211 R1301 R1411 R1412 R1417 R1420-R1430 R2127 R2130 R2134 R2139 R2140 = RES: RES MF ZERO OHM 1/16W 5% 0402; AGILE_PN: 470-75394; CAD_APPROVED: Yes; FPLIST: RC0402_25,RC0402_HD,RC0402_X2,0402_CC; HEIGHT: 0.45 MM; MFG_NAME01: YAGEO AMERICA; MFG_PN01: RC0402JR-070RL; ROHS: Yes; Tolerance: 5%
R907 R908 R910 R911 R1404 R1435 R2141-R2144 = RES: RES MF ZERO OHM 1/16W 5% 0402; AGILE_PN: 470-75394; ASSY_OPT: DNP; CAD_APPROVED: Yes; FPLIST: RC0402_25,RC0402_HD,RC0402_X2,0402_CC; HEIGHT: 0.45 MM; MFG_NAME01: YAGEO AMERICA; MFG_PN01: RC0402JR-070RL; ROHS: Yes; Tolerance: 5%
R913 R1303 R1305 R1402 = RES: RES MF 100K 1/16W 5% 0402; AGILE_PN: 470-75597; CAD_APPROVED: Yes; FPLIST: RC0402_25,RC0402_HD,0402_CC; HEIGHT: 0.40 MM; MFG_NAME01: VENKEL COMPANY; MFG_PN01: CR0402-16W-104JT; ROHS: Yes; Temp Range: -55C to +155C; Temp_Range: -55C to +155C; Tolerance: 5%
R914 R1207 R1304 R2126 R2132 R2145 = RES: RES MF 10K 1/16W 5% 0402; AGILE_PN: 470-75557; CAD_APPROVED: Yes; FPLIST: RC0402_25,RC0402_HD,0402_CC; HEIGHT: 0.4 MM; MFG_NAME01: VISHAY INTERTECHNOLOGY; MFG_PN01: CRCW040210K0JNED; ROHS: Yes; Tolerance: 5%
C1202 C1203 C1207 C1209 = CAP_NP: CAP CER 1.0UF 10V 10% X5R 0402; AGILE_PN: 150-75772; CAD_APPROVED: Yes; FPLIST: CC0402_25,CC0402_HD,0402_CC; HEIGHT: 0.6MM; MFG_NAME01: YAGEO AMERICA; MFG_PN01: CC0402KRX5R6BB105; Package Size: 0402; ROHS: Yes; Rated Voltage: 10V; Temp Range: -55C to +85C; Tolerance: 10%; VOLTAGE: 10V
C1204 C1206 C1210 C1212 = CAP_NP: CAP CER 56PF 50V 5% C0G 0402; AGILE_PN: 150-30269; CAD_APPROVED: Yes; FPLIST: CC0402_25,CC0402_HD,0402_CC; HEIGHT: 0.55 MM; MFG_NAME01: VENKEL COMPANY; MFG_PN01: C0402C0G500-560JNE; ROHS: Yes; Rated Voltage: 50V; Temp Range: -55C to +125C; Tolerance: 5%; VOLTAGE: 50V
C1205 C1211 = CAP_NP: CAP CER 0.01UF 50V 10% X7R 0402; AGILE_PN: 150-30114; ASSY_OPT: DNP; CAD_APPROVED: Yes; FPLIST: CC0402_25,CC0402_HD,0402_CC; HEIGHT: 0.55 MM; MFG_NAME01: MURATA; MFG_PN01: GRM155R71H103KA88D; ROHS: Yes; Rated Voltage: 50V; Temp Range: -55C to +125C; Tolerance: 10%; VOLTAGE: 50V
J1201 = CON_W2B_8P: CON 8 PLUG RA SHRD SMT 1.25MM SP 142H AU; AGILE_PN: 211-79668; CAD_APPROVED: Yes; HEIGHT: 3.45MM; MFG_NAME01: SHENZHEN ATOM TECHNOLOGY CO.,LTD; MFG_PN01: WF1250801200; ROHS: Yes
L1201 L1202 = DATA_CHOKE: IND CHK 100uH 150mA -30/+50% AEC-Q200 1812; 3D_Mechanical_Footprint_File: http://fcl.am.freescale.net/ALLEGRO/step/ind_1812_4p.STEP; AGILE_PN: 180-78098; ASSY_OPT: DNP; CAD_APPROVED: Yes; HEIGHT: 3MM; MFG_NAME01: EPCOS; MFG_PN01: B82789C0104N002; PART_TYPE: CHOKE; ROHS: Yes; Tolerance: -30/+50%
R1204 R1205 R1209 R1210 = RES: RES MF 62.0 OHM 1/4W 1% AEC-Q200 0805; AGILE_PN: 470-78674; CAD_APPROVED: Yes; FPLIST: RC0805_OV,RC0805,0805_CC; HEIGHT: 0.6 MM; MFG_NAME01: KOA SPEER; MFG_PN01: RK73H2ATTD62R0F; ROHS: Yes; Tolerance: 1%
TVS1201 TVS1401-TVS1404 = DIODE_BIDIR: DIODE BIDIR ESD PROT 3.5pF 5V 1A SOD-962; 3D_Mechanical_Footprint_File: http://fcl.am.freescale.net/ALLEGRO/step/dsn0603-2.STEP; AGILE_PN: 480-79836; CAD_APPROVED: Yes; HEIGHT: 0.32MM; MFG_NAME01: NEXPERIA; MFG_PN01: PESD5V0V1BSF,315; Temp Range: -55°C to +150°C
U1201 U1202 = TJA1044GT_3: IC XCVR CAN HS 4.75-5.25V AEC-Q100 SO8; 3D_Mechanical_Footprint_File: http://fcl.am.freescale.net/ALLEGRO/step/so8_1p27_4x5.step; AGILE_PN: 312-81885; CAD_APPROVED: Yes; HEIGHT: 1.75MM; MFG_NAME01: NXP SEMICONDUCTORS; ROHS: Yes; VOLTAGE: 4.75-5.25V
U1203 = SRV05-4: DIODE TVS ARRAY 12A 5V 300W SOT23_S6; 3D_Mechanical_Footprint_File: http://fcl.am.freescale.net/ALLEGRO/step/SOT23_S6.STEP; AGILE_PN: 480-75205; CAD_APPROVED: Yes; HEIGHT: 1.45mm; MFG_NAME01: SEMTECH CORP; MFG_PN01: SRV05-4.TCT; ROHS: Yes; Rated Voltage: 5V
C1303 C2161 = CAP_NP: CAP CER 1uF 16V 10% X5R 0402; AGILE_PN: 150-78973; ASSY_OPT: <ASSY_OPT>; CAD_APPROVED: Yes; FPLIST: CC0402_25,CC0402_HD,0402_CC; HEIGHT: 0.55 MM; MFG_NAME01: YAGEO; MFG_PN01: CC0402KRX5R7BB105; ROHS: Yes; Rated Voltage: 16V; Temp Range: -55C to +85C; Tolerance: 10%; VOLTAGE: 16V
C1305 C1310 C1404 C1409 C1414 C1417 = CAP_NP: CAP CER 4.7UF 6.3V 20% X5R 0402; AGILE_PN: 150-78463; CAD_APPROVED: Yes; FPLIST: CC0402_25,CC0402_HD,0402_CC; HEIGHT: 0.65MM; MFG_NAME01: TDK; MFG_PN01: C1005X5R0J475M; ROHS: Yes; Rated Voltage: 6.3V; Temp Range: -55C to +85C; Tolerance: 20%; VOLTAGE: 6.3V; voltage rating: 6.3V
R1302 R2137 = RES: RES MF 100K 1/16W 5% 0402; AGILE_PN: 470-75597; ASSY_OPT: DNP; CAD_APPROVED: Yes; FPLIST: RC0402_25,RC0402_HD,0402_CC; HEIGHT: 0.40 MM; MFG_NAME01: VENKEL COMPANY; MFG_PN01: CR0402-16W-104JT; ROHS: Yes; Temp Range: -55C to +155C; Temp_Range: -55C to +155C; Tolerance: 5%
R1306 R1307 R2138 = RES: RES MF 4.7K 1/16W 5% 0402; AGILE_PN: 470-75626; CAD_APPROVED: Yes; FPLIST: RC0402_25,RC0402_HD,0402_CC; HEIGHT: 0.41mm; MFG_NAME01: NIC COMPONENTS CORP; MFG_PN01: NRCL04J472TRF; ROHS: Yes; Tolerance: 5%
R1419 R2133 = RES: RES MF 1.0K 1/16W 5% 0402; AGILE_PN: 470-75555; ASSY_OPT: DNP; CAD_APPROVED: Yes; FPLIST: RC0402_25,RC0402_HD,RC0402_X2,0402_CC; HEIGHT: 0.41mm; MFG_NAME01: VISHAY INTERTECHNOLOGY; MFG_PN01: CRCW04021K00JNED; ROHS: Yes; Tolerance: 5%
R1413 R1414 R2135 R2136 R2148 = RES: RES MF 1.0K 1/16W 5% 0402; AGILE_PN: 470-75555; CAD_APPROVED: Yes; FPLIST: RC0402_25,RC0402_HD,RC0402_X2,0402_CC; HEIGHT: 0.41mm; MFG_NAME01: VISHAY INTERTECHNOLOGY; MFG_PN01: CRCW04021K00JNED; ROHS: Yes; Tolerance: 5%
TP1301-TP1303 = TESTLOOP: TEST POINT PAD 0.5MM DIA SMT, NO PART TO ORDER; AGILE_PN: 211-77484; CAD_APPROVED: Yes; HEIGHT: 0.1MM; ROHS: Yes
U1301 = FXLS8962AF_DFN10: IC ACCELEROMETER 3-AXIS 12BIT 1.71-3.6V AEC-Q100 DFN10; 3D_Mechanical_Footprint_File: http://fcl.am.freescale.net/ALLEGRO/step/dfn_10_0p4_2x2.STEP; AGILE_PN: TMP-CIP-7425; CAD_APPROVED: Yes; HEIGHT: 1 MM; MFG_NAME01: NXP SEMICONDUCTORS; PRE_APN: 312-83141; ROHS: Yes; Temp Range: -40  °C to +105 °C
U1302 = MAG3112_DFN_10P: OBSOLETE USE 312-80418 BUT FOOTPRINT & LOGIC SYMBOL IS DIFFERENT; AGILE_PN: 312-79970; ASSY_OPT: DNP; CAD_APPROVED: Yes; FPLIST: DFN_10_0P4_2X2_B,DFN_10_0P4_2X2_A,dfn_10_0p4_2x2_a_nsp; HEIGHT: 0.9MM; MFG_NAME01: FREESCALE SEMICONDUCTOR; MFG_PN01: MAG3110FC; ROHS: Yes; VOLTAGE: 1.95-3.6V
U1303 = FXAS21002CQ_QFN_24P: OBSOLETE IC XTRINSIC 3-AXIS DIGITAL GYROSCOPE 1.95-3.6V QFN24; AGILE_PN: 312-81029; ASSY_OPT: DNP; CAD_APPROVED: Yes; HEIGHT: 1.1 MM; MFG_NAME01: FREESCALE SEMICONDUCTOR; ROHS: Yes; VOLTAGE: 1.95-3.6V
C268 C269 = CAP_NP: CAP CER 0.1uF 50V 10% X7R AEC-Q200 0402; AGILE_PN: 150-79461; CAD_APPROVED: Yes; EN: 102-1-02300; FPLIST: CC0402_25,CC0402_HD,0402_CC; HEIGHT: 0.55MM; MFG_NAME01: MURATA; MFG_PN01: GCM155R71H104KE02D; Package Size: 0402; ROHS: Yes; Rated Voltage: 50V; TOL: 10%; Temp Range: -55C to +125C; Tolerance: 10%; VOLTAGE: 50V
C272 C273 = CAP_NP: CAP CER 1000PF 50V X7R 5% 0402; AGILE_PN: 150-75774; ASSY_OPT: DNP; CAD_APPROVED: Yes; EN: 102-1-00054; FPLIST: CC0402_25,CC0402_HD,0402_CC; HEIGHT: 0.6MM; MFG_NAME01: CAPAX TECHNOLOGIES INC.; MFG_PN01: 0402X102J500SNT; Package Size: 0402; Package Type: Tape&reel; ROHS: Yes; Rated Voltage: 50V; TOL: 5%; Temp Range: -55C to +125C; Tolerance: 5%; VOLTAGE: 50V
C587 C590 C591 = CAP_NP: CAP CER 2.2uF 6.3V 10% X5R 0402; AGILE_PN: 150-79454; CAD_APPROVED: Yes; FPLIST: CC0402_25,CC0402_HD,0402_CC; HEIGHT: 0.55MM; MFG_NAME01: MURATA; MFG_PN01: GRM155R60J225KE01D; ROHS: Yes; Rated Voltage: 6.3V; Temp Range: -55C to +85C; Tolerance: 10%; VOLTAGE: 6.3V
C1401 C1405-C1408 C2156 = CAP_NP: CAP CER 4.7UF 10V 10% X5R 0603; AGILE_PN: 150-77975; CAD_APPROVED: Yes; FPLIST: CC0603_OV,CC0603,0603_CC; HEIGHT: 0.9MM; MFG_NAME01: FENGHUA; MFG_PN01: 0603X475K100NT; Package Size: 0603; Package Type: tape & reel; ROHS: Yes; Rated Voltage: 10V; SIGNAL_MODEL: DEFAULT_CAPACITOR_4.7e+06pF_2_1; Temp Range: -55C to +85C; Tolerance: 10%; VOLTAGE: 10V; WVDC: 16V
C1415 C1418 = CAP_NP: CAP CER 1uF 16V 10% X5R 0402; AGILE_PN: 150-78973; ASSY_OPT: DNP; CAD_APPROVED: Yes; FPLIST: CC0402_25,CC0402_HD,0402_CC; HEIGHT: 0.55 MM; MFG_NAME01: YAGEO; MFG_PN01: CC0402KRX5R7BB105; ROHS: Yes; Rated Voltage: 16V; Temp Range: -55C to +85C; Tolerance: 10%; VOLTAGE: 16V
C1416 C1419 C1425-C1428 = CAP_NP: CAP CER 15PF 16V 5% C0G 0402; AGILE_PN: 150-75720; CAD_APPROVED: Yes; FPLIST: CC0402_25,CC0402_HD,0402_CC; HEIGHT: 0.55MM; MFG_NAME01: KEMET; MFG_PN01: C0402C150J4GAC; Package Size: 0402; ROHS: Yes; Rated Voltage: 16V; Temp Range: -55C to +125C; Tolerance: 5%; VOLTAGE: 16V
C1422 = CAP_NP: CAP CER 4.7UF 6.3V 20% X5R 0402; AGILE_PN: 150-78463; ASSY_OPT: DNP; CAD_APPROVED: Yes; FPLIST: CC0402_25,CC0402_HD,0402_CC; HEIGHT: 0.65MM; MFG_NAME01: TDK; MFG_PN01: C1005X5R0J475M; ROHS: Yes; Rated Voltage: 6.3V; Temp Range: -55C to +85C; Tolerance: 20%; VOLTAGE: 6.3V; voltage rating: 6.3V
C1429-C1438 = CAP_NP: CAP CER 15PF 16V 5% C0G 0402; AGILE_PN: 150-75720; ASSY_OPT: DNP; CAD_APPROVED: Yes; FPLIST: CC0402_25,CC0402_HD,0402_CC; HEIGHT: 0.55MM; MFG_NAME01: KEMET; MFG_PN01: C0402C150J4GAC; Package Size: 0402; ROHS: Yes; Rated Voltage: 16V; Temp Range: -55C to +125C; Tolerance: 5%; VOLTAGE: 16V
J1401 = CONN_AUDIOJACK_6P: CON 6 AUD JACK RA SMT -- 191H AU; AGILE_PN: 211-79704; CAD_APPROVED: Yes; HEIGHT: 4.85 MM; MFG_NAME01: SHENZHEN ATOM TECHNOLOGY CO.,LTD; Package Type: TH; ROHS: Yes
J1402 J1403 = CON1X2_TAB: CON 2 PLUG RA SHRD SMT 1.25MM SP 142H --; AGILE_PN: 211-79678; CAD_APPROVED: Yes; HEIGHT: 3.6MM; MFG_NAME01: SHENZHEN ATOM TECHNOLOGY CO.,LTD; ROHS: Yes
L1403 = BEAD_0: IND FER BEAD 120OHM@100MHZ 2A 25% 0603; AGILE_PN: 180-30008; CAD_APPROVED: Yes; FPLIST: IND_0603,0603_CC; HEIGHT: 0.95MM; MFG_NAME01: MURATA; MFG_PN01: BLM18PG121SH1; PART_TYPE: FERRITE; ROHS: Yes; Tolerance: 25%
L2103 L2104 = BEAD_0: IND FER BEAD 120OHM@100MHZ 2A 25% 0603; AGILE_PN: 180-78419; CAD_APPROVED: Yes; FPLIST: IND_0603,0603_CC; HEIGHT: 0.95MM; MFG_NAME01: MURATA; MFG_PN01: BLM18PG121SN1D; ROHS: Yes
P1401 = MIC_POM: AUDIO DEVICE MIC 0.5MA 2V 38-48+/-3dB 2.2KOHM 6MM TH; 3D_Mechanical_Footprint_File: http://fcl.am.freescale.net/ALLEGRO/step/mic_WM-63PR.step; AGILE_PN: 510-77987; CAD_APPROVED: Yes; HEIGHT: 2.4MM; MFG_NAME01: SOBERTON INC; ROHS: Yes
R1407 R1431-R1434 = RES: RES MF 51 OHM 1/16W 1% 0402; AGILE_PN: 470-82836; CAD_APPROVED: Yes; HEIGHT: 0.40 MM; MFG_NAME01: YAGEO AMERICA; MFG_PN01: RC0402FR-0751RL; Package Size: 0402 (1005 Metric); ROHS: Yes; Temp Range: -55°C to 155°C; Tolerance: 1%
R1410 R1821 = RES: RES MF 20.0OHM 1/10W 1% 0603; AGILE_PN: 470-75405; CAD_APPROVED: Yes; FPLIST: RC0603_OV,RC0603,0603_CC; HEIGHT: 0.55 MM; MFG_NAME01: BOURNS; MFG_PN01: CR0603-FX-20R0ELF; ROHS: Yes; SIGNAL_MODEL: DEFAULT_RESISTOR_20OHM_2_1; Tolerance: 1%
R1415 R1416 = RES: RES MF 1.2k 1/16W 1% AEC-Q200 0402; AGILE_PN: 470-82619; CAD_APPROVED: Yes; FPLIST: RC0402_25,RC0402_HD,0402_CC; HEIGHT: 0.4MM; MFG_NAME01: VISHAY INTERTECHNOLOGY; MFG_PN01: CRCW04021K20FKED; Package Size: 0402 [1005 Metric]; Package Type: Surface Mount; ROHS: Yes; Temp Range: -55°C to 155°C; Tolerance: 1%
R1418 = RES: RES MF 10K 1/16W 5% 0402; AGILE_PN: 470-75557; ASSY_OPT: DNP; CAD_APPROVED: Yes; FPLIST: RC0402_25,RC0402_HD,0402_CC; HEIGHT: 0.4 MM; MFG_NAME01: VISHAY INTERTECHNOLOGY; MFG_PN01: CRCW040210K0JNED; ROHS: Yes; TOL: 5%; Tolerance: 5%
R1436 = RES: RES MF ZERO OHM 1/16W 5% 0402; AGILE_PN: 470-75394; ASSY_OPT: <ASSY_OPT>; CAD_APPROVED: Yes; FPLIST: RC0402_25,RC0402_HD,RC0402_X2,0402_CC; HEIGHT: 0.45 MM; MFG_NAME01: YAGEO AMERICA; MFG_PN01: RC0402JR-070RL; ROHS: Yes; Tolerance: 5%
R2146 R2147 = RES: RES MF 10K 1/16W 5% 0402; AGILE_PN: 470-75557; ASSY_OPT: DNP; CAD_APPROVED: Yes; FPLIST: RC0402_25,RC0402_HD,0402_CC; HEIGHT: 0.4 MM; MFG_NAME01: VISHAY INTERTECHNOLOGY; MFG_PN01: CRCW040210K0JNED; ROHS: Yes; Tolerance: 5%
TP1022 TP1030 TP1031 = T_POINT_R: TEST POINT PAD .035 SMT, no part to order; AGILE_PN: 510-75618; CAD_APPROVED: Yes; HEIGHT: 0.1MM; ROHS: Yes
U1401 = WM8962_BGA_49P: IC AUDIO CODEC 24BIT DAC 2 CH ADC 1.8V BGA49; 3D_Mechanical_Footprint_File: http://fcl.am.freescale.net/ALLEGRO/step/BGA49_0P5_3P62X4.STEP; AGILE_PN: 315-80353; CAD_APPROVED: Yes; HEIGHT: 0.75MM; MFG_NAME01: CIRRUS LOGIC; ROHS: Yes; VOLTAGE: 1.8V
U2107 = TCA9416DDFR_SOT23_8P: IC DUAL BI I2S VOLTAGE TRANSLATOR 1.08-3.6V SOT23-8; 3D_Mechanical_Footprint_File: http://fcl.am.freescale.net/ALLEGRO/step/sot-23-8-thin.STEP; AGILE_PN: TMP-CIP-14120; CAD_APPROVED: Yes; HEIGHT: 1.1 MM; MFG_NAME01: Texas Instruments; PRE_APN: 312-83867; ROHS: Yes; Temp Range: -40  °C to +125 °C

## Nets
AVDD_1V8: C2156.1 L2104.2 U1401.D6(AVDD)
DVDD_1V8: L2104.1 R2130.1 R2140.1 ; also on sheet 15
GND: C272.2 C273.2 C590.2 C591.2 C901.2 C902.2 C903.2 C904.2 C905.2 C1201.2 C1202.2 C1203.2 C1204.1 C1205.2 C1206.2 C1207.2 C1208.2 C1209.2 C1210.1 C1211.2 C1212.2 C1302.2 C1303.2 C1305.2 C1306.2 C1307.2 C1308.2 C1309.2 C1310.2 C1311.2 C1312.2 C1313.2 C1314.2 C1401.2 C1402.2 C1403.2 C1404.2 C1405.2 C1406.2 C1407.2 C1408.2 C1409.2 C1414.2 C1415.2 C1416.1 C1417.2 C1418.2 C1419.1 C1425.2 C1426.2 C1427.2 C1428.2 C1429.1 C1430.1 C1431.1 C1432.1 C1435.2 C1436.2 C1437.2 C1438.2 C2156.2 C2161.2 J901.9 J901.18 J901.27 J901.31 J901.33 J901.44 J901.S1 J901.S2 J1201.2 J1201.5 J1201.8 J1201.9 J1201.10 J1401.1 J1402.3 J1402.4 J1403.3 J1403.4 R914.2 R1303.2 R1410.2 R1422.1 R1821.2 R2126.2 R2127.2 R2132.2 R2134.1 R2135.2 R2136.2 R2148.2 TVS1201.1(C1) TVS1401.1(C1) TVS1402.1(C1) TVS1403.1(C1) TVS1404.1(C1) U1201.2(GND) U1202.2(GND) U1203.2(GND) U1301.9(INTF_SEL) U1301.10(GND) U1302.5(GND1) U1302.10(GND2) U1303.1(GND1) U1303.5(GND2) U1303.6(RSVD1) U1303.7(RSVD2) U1303.8(~{I2C}/SPI) U1303.9(RSVD3) U1303.10(RSVD4) U1303.13(SA0/MISO) U1303.14(GND3) U1303.19(GND4) U1303.20(RSVD5) U1303.21(RSVD6) U1303.22(RSVD7) U1303.23(RSVD8) U1303.24(RSVD9) U1401.B1(SPKGND1) U1401.C1(SPKGND2) U1401.C7(CPGND) U1401.D7(AGND) U1401.F2(CIFMODE) U1401.F3(DGND) U1401.G5(PLLGND) U2107.6(GND) ; also on sheet 3 4 12 13 14 15 16 17 18
VDD_1V8: C1407.1 C1408.1 R2140.2 U1401.C6(CPVDD) U1401.G4(PLLVDD)
ACC_INT: R1302.2 U1301.8(INT1/MOT_DET) ; also on sheet 3
AUD_INT: R1435.1 R1436.1 ; also on sheet 3
BLT_PWM: L903.1 ; also on sheet 3
CAN1_2_STBY: R1207.2 U1201.8(STB) U1202.8(STB) ; also on sheet 3
CAN1_H: C1204.2 J1201.4 L1201.4(OUT2) R1203.2 R1204.1 U1203.1(I/O1)
CAN1_L: C1206.1 J1201.3 L1201.2(IN2) R1205.2 R1206.2 U1203.3(I/O3)
CAN1_RX: U1201.4(RXD) ; also on sheet 3
CAN1_TX: U1201.1(TXD) ; also on sheet 3
CAN1H: L1201.3(OUT1) R1203.1 U1201.7(CANH)
CAN1L: L1201.1(IN1) R1206.1 U1201.6(CANL)
CAN2_H: C1210.2 J1201.7 L1202.4(OUT2) R1208.2 R1209.1 U1203.6(I/O6)
CAN2_L: C1212.1 J1201.6 L1202.2(IN2) R1210.2 R1211.2 U1203.4(I/O4)
CAN2_RX: U1202.4(RXD) ; also on sheet 3
CAN2_TX: U1202.1(TXD) ; also on sheet 3
CAN2H: L1202.3(OUT1) R1208.1 U1202.7(CANH)
CAN2L: L1202.1(IN1) R1211.1 U1202.6(CANL)
CAN_VDD_5V: C1201.1 C1203.1 C1208.1 C1209.1 R1201.2 U1201.3(VCC) U1202.3(VCC)
CAN_VIO_3V3: C1202.1 C1207.1 R1202.1 R1207.1 U1201.5(VIO) U1202.5(VIO)
CODEC_I2C_SCL: R1411.2 R2143.2 R2146.2 U1401.F1(SCLK)
CODEC_I2C_SDA: R1412.2 R2144.2 R2147.2 U1401.E2(SDA)
CPCA: C587.1 U1401.B6(CPCA)
CPCB: C587.2 U1401.B7(CPCB)
CPVOUTN: C591.1 U1401.A7(CPVOUTN)
CPVOUTP: C590.1 U1401.A6(CPVOUTP)
DCDC_3V3: Q901.2(SOURCE) R901.1 R913.1 ; also on sheet 3 4 12 16 17 18
DCDC_5V: R1201.1 ; also on sheet 12 15 17 18
DCVDD_1V8: C1403.1 R2130.2 U1401.G2(DCVDD)
ECSPI4_MISO: R910.1 ; also on sheet 3 14 18
ECSPI4_MOSI: R908.1 ; also on sheet 3 14 18
ECSPI4_SCLK: R907.1 ; also on sheet 3 14 18
ECSPI4_SS0: R911.1 ; also on sheet 3 14 18
FSL_GYRO_INT1: TP1302.1(Pin1) U1303.3(INT1)
FSL_GYRO_INT2: TP1303.1(Pin1) U1303.2(INT2/PWR_CTRL)
HP_FB: R2127.1 U1401.B4(HPOUTFB)
HP_JD: R1404.1 R2148.1 U1401.G1(GPIO5)
HP_L: C269.2 L1401.1 R2126.1 U1401.B5(HPOUTL)
HP_MIC1N: C1419.2 C1421.1 U1401.C4(IN1L)
HP_MIC1P: C1424.1 C1425.1 U1401.F5(IN3L)
HP_R: C268.2 L1402.1 R2132.1 U1401.A5(HPOUTR)
HPL_ZOBEL: C269.1 R1410.1
HPR_ZOBEL: C268.1 R1821.1
I2C1_SCL: R1306.2 U1301.5(SCL/SCLK) U1302.7(SCL) U1303.11(SCL/SCLK) ; also on sheet 3
I2C1_SDA: R1307.2 U1301.4(SDA/SPI_MOSI/SPI_DATA) U1302.6(SDA) U1303.12(SDA/MOSI/SPI_DIO) ; also on sheet 3
I2C2_SCL: L904.1 R1411.1 R2141.1 ; also on sheet 3 4 12 18
I2C2_SDA: L905.1 R1412.1 R2142.1 ; also on sheet 3 4 12 18
INT2: R2133.2 R2135.1 R2137.2 TP1301.1(Pin1) U1301.2(BT_MODE) U1301.6(INT2/EXT_TRIG/BOOT_OUT)
JTAG_nTRST: R1433.1 ; also on sheet 3 16
JTAG_TCK: R1431.1 ; also on sheet 3 16
JTAG_TDI: R1407.1 ; also on sheet 3 16
JTAG_TDO: R1432.1 ; also on sheet 3 16
JTAG_TMS: R1434.1 ; also on sheet 3 16
LCD_DATA0: R919.1 ; also on sheet 3 12
LCD_DATA1: R920.1 ; also on sheet 3 12
LCD_DATA2: R921.1 ; also on sheet 3 12
LCD_DATA3: R922.1 ; also on sheet 3 12
LCD_DATA4: R923.1 ; also on sheet 3 12
LCD_DATA5: R924.1 ; also on sheet 3 12
LCD_DATA6: R925.1 ; also on sheet 3 12
LCD_DATA7: R926.1 ; also on sheet 3 12
LCD_DATA8: R927.1 ; also on sheet 3 12
LCD_DATA9: R928.1 ; also on sheet 3 12
LCD_DATA10: R929.1 ; also on sheet 3 12
LCD_DATA11: R930.1 ; also on sheet 3 12
LCD_DATA12: R931.1 ; also on sheet 3 12
LCD_DATA13: R932.1 ; also on sheet 3 12
LCD_DATA14: R933.1 ; also on sheet 3 12
LCD_DATA15: R934.1 ; also on sheet 3 12
LCD_DATA16: R935.1 ; also on sheet 3 12
LCD_DATA17: R936.1 ; also on sheet 3 12
LCD_DATA18: R937.1 ; also on sheet 3 12
LCD_DATA19: R938.1 ; also on sheet 3 12
LCD_DATA20: R939.1 ; also on sheet 3 12
LCD_DATA21: R940.1 ; also on sheet 3 12
LCD_DATA22: R941.1 ; also on sheet 3 12
LCD_DATA23: R942.1 ; also on sheet 3 12
LCD_DE: R943.1 ; also on sheet 3 12
LCD_DISP: R917.1 ; also on sheet 3
LCD_HSYNC: R944.1 ; also on sheet 3 12
LCD_nPWREN: D901.A ; also on sheet 3
LCD_PCLK: R946.1 ; also on sheet 3 12
LCD_VSYNC: R945.1 ; also on sheet 3 12
MAG_INT: R1303.1 U1302.9(INT1)
MAIN_MIC2N: C1423.2 C1428.1 U1401.D4(IN1R)
MAIN_MIC2P: C1416.2 C1420.2 U1401.E5(IN2R)
MICBIAS: C1404.1 R1413.1 R1414.1 U1401.A4(MICBIAS)
SPK_LN: R1425.1 U1401.B3(SPKOUTLN)
SPK_LP: R1429.1 U1401.A1(SPKOUTLP)
SPK_RN: R1423.1 U1401.C3(SPKOUTRN)
SPK_RP: R1427.1 U1401.B2(SPKOUTRP)
USB_OTG1_OC: R906.1 ; also on sheet 3 17 18
USB_OTG1_PWR: R903.1 ; also on sheet 3 15 17 18
USB_OTG2_OC: R904.1 ; also on sheet 3 17 18
USB_OTG2_PWR: R905.1 ; also on sheet 3 17 18
VAUD_3V3: C1401.1 C1402.1 C2161.1 R1402.1 R2139.2 R2145.1 R2146.1 R2147.1 U1401.A3(MICVDD) U1401.G3(DBVDD) U2107.3(VCCA) U2107.7(VCCB)
VENET_3V3: J1201.1 R1202.2 R1301.1 R2139.1 TVS1201.2(C2) ; also on sheet 3 4 13 14 15 18
VLCD_3V3: L901.1 Q901.3(DRAIN) R901.2
VSENSOR_3V3: C1302.1 C1303.1 C1305.1 C1306.1 C1307.1 C1310.1 C1311.1 C1312.1 R1301.2 R1302.1 R1304.1 R1305.1 R1306.1 R1307.1 R2133.1 R2137.1 R2138.1 U1301.1(VDD) U1302.2(VDD) U1302.8(VDDIO) U1303.15(VDD) U1303.18(VDDIO)
VSPK_5V: C1405.1 C1406.1 L2103.2 U1401.A2(SPKVDD1) U1401.C2(SPKVDD2)
VSYS: L902.1 L2103.1 ; also on sheet 3 4 15
xnur: J901.35 R904.2
xpul: J901.34 R903.2
ynlr: J901.37 R906.2
ypll: J901.36 R905.2
N97015722: J1401.4 L1403.2 TVS1404.2(C2)
N97015748: J1401.5 R1402.2 R1404.2 R1436.2 TVS1402.2(C2)
N97015788: C272.1 J1401.2 L1401.2 TVS1401.2(C2)
N97015810: C273.1 J1401.3 L1402.2 TVS1403.2(C2)
N97015895: C1422.2 R1421.1 R1422.2
N97016058: C1409.1 U1401.C5(VMIDC)
N97016158: C1423.1 R1418.2 R1420.2 R1421.2
N97016160: C1420.1 R1415.2 R1417.2 R1418.1
N97016178: C1414.1 C1415.1 C1422.1 R1414.2 R1415.1
N97016638: C1424.2 C1426.1 C1427.1 L1403.1 R1416.2 R1419.2
N97016689: C1417.1 C1418.1 R1413.2 R1416.1
N97016733: C1421.2 R1419.1 R2134.2
N97033876: C1313.1 U1303.16(VREGD)
N97034198: C1314.1 R1304.2 U1303.4(~{RST})
N97034207: R1305.2 U1303.17(~{SPI_CS})
N97034229: C1309.1 U1302.4(CAP_R)
N97034320: C1308.1 U1302.1(CAP_A)
N97122742: C1205.1 R1204.2 R1205.1
N97124588: C1211.1 R1209.2 R1210.1
N97419423: R1407.2 U1401.E1(BCLK)
N97614525: C1429.2 R1423.2 R1424.1
N97614556: C1435.1 R1427.2 R1428.1
N97614560: C1430.2 C1433.1 J1402.1 R1424.2
N97614565: C1433.2 C1436.1 J1402.2 R1428.2
N97617364: P1401.1(Out) R1417.1
N97617373: P1401.2(GND) R1420.1
N97687801: C1431.2 R1425.2 R1426.1
N97687808: C1437.1 R1429.2 R1430.1
N97687812: C1432.2 C1434.1 J1403.1 R1426.2
N97687814: C1434.2 C1438.1 J1403.2 R1430.2
N98672077: R1431.2 U1401.D2(ADCDAT)
N98806492: C901.1 C904.1 J901.47 J901.48 L902.2
N98806494: C902.1 C903.1 J901.46 L901.2 R912.1
N98806512: J901.40 R910.2
N98806513: J901.41 R911.2
N98806514: J901.45 R912.2
N98806535: J901.38 R907.2
N98806536: J901.39 R908.2
N98998296: D901.C Q901.1(GATE) R913.2 R914.1
N99177484: R1432.2 U1401.D3(LRCLK)
N99177512: R1433.2 U1401.D1(DACDAT)
N99177533: R1434.2 U1401.G7(MCLK/XTI)
N99195829: R1435.2 U1401.E3(~{CS}/GPIO6)
N99261871: J901.4 R922.2
N99261874: J901.3 R921.2
N99261877: J901.1 R919.2
N99261880: J901.2 R920.2
N99261883: J901.5 R923.2
N99261886: J901.6 R924.2
N99261889: J901.7 R925.2
N99261892: J901.8 R926.2
N99262106: J901.16 R933.2
N99262109: J901.10 R927.2
N99262112: J901.17 R934.2
N99262115: J901.15 R932.2
N99262118: J901.14 R931.2
N99262121: J901.13 R930.2
N99262124: J901.12 R929.2
N99262127: J901.11 R928.2
N99262341: J901.20 R936.2
N99262344: J901.21 R937.2
N99262347: J901.22 R938.2
N99262350: J901.26 R942.2
N99262353: J901.19 R935.2
N99262356: J901.23 R939.2
N99262359: J901.24 R940.2
N99262362: J901.25 R941.2
N99265725: J901.28 R943.2
N99265746: J901.29 R944.2
N99265767: J901.30 R945.2
N99265792: J901.32 R946.2
N99336104: J901.49 R917.2
N99363439: C905.1 J901.50 L903.2
N99370076: J901.43 L905.2
N99370078: J901.42 L904.2
N101118774: TP1030.1(TP) U1401.F7(XTO)
N101119545: TP1022.1(TP) U1401.E4(CLKOUT2/GPIO2)
N101119582: TP1031.1(TP) U1401.G6(CLKOUT5)
N101178971: R2136.1 U1301.3(SA0/SPI_MISO)
N101181789: R2138.2 U1301.7(~{SPI_CS}/WAKE_UP)
N101646107: R2144.1 U2107.5(SDA_B)
N101646110: R2143.1 U2107.8(SCL_B)
N101646358: R2141.2 U2107.1(SCL_A)
N101646361: R2142.2 U2107.4(SDA_A)
N101646936: R2145.2 U2107.2(OE)

Not connected (* = marked no-connect by the designer): J1401 6; U1203 5(VCC); U1302 3(NC)*; U1401 D5(IN2L)* E6(IN4L)* E7(IN4R)* F4(CLKOUT3/GPIO3)* F6(IN3R)*

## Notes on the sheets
sheet 5
- Audio Codec
- Codec
- OFF, SLEEP MODE
- DCVDD
  DBVDD
  MICVDD
  AVDD
  PLLVDD
  CPVDD
  SPKVDD
- 1.62V - 1.8V
  1.62V - 3.6V
  1.70V - 3.6V
  1.70V - 2.0V
  1.70V - 2.0V
  1.70V - 2.0V
  1.70V - 5.5V
- HP JACK
- # HP_DET:
      LOW : REMOVE
      HIGH : PLUG
- HP_L
- HP_DET
- HP_R
- layout note:
  C587 should be as close
  to the WM8962 as
  possible.
- MIC
- EARTH
- # I2C ADDR:  0011010x
- 3.5mm POLE
- i
- o
- HSL
- HSR
- MIC
- GND
- Layout note:
  Zobel Networks(C269, C268
  ,R1410,R1821) close to WM8962B
- Layout note:
  Widen the trace SPKVDD_5V0
  Max ~0.6A
- HP MIC
- Main Board MIC
- SPK
sheet 6
- Motion Sensor 9-axis
- Accelerometer
- U1301: FXLS8974CFR3
  Default: Motion Detection disabled
  For Motion Detection to be enabled,
  Populate: R2133, R2137, R1302
  DNP: R2135, R2138
- # I2C Secondary ADDR:
  SA0 = 0;  0011_000
- e-Compass
- VDD:1.95V to 3.6V
  VDDIO:1.65V to Vdd
- Active 'H'
- # Current consumption:
  IddStby: 2uA
  Idd: 900uA
- # I2C ADDR: Write = 0x1C; Read = 0x1D;
- Gyroscope
- # I2C ADDR:
      SA0 = '0': 0x20;
- # Current consumption:
  IddAct: 5mA
  IddStby: 2uA
sheet 7
- High Speed CAN Transceiver
- CAN CN
- # FSL High Speed CAN Transceiver
- CAN #1
- Standby: 5 uA
- Cable Buy
- CAN #2
sheet 8
- LCD CN
- LCD IF
- B0
- B1
- B2
- B3
- B4
- B5
- B6
- B7
- GND
- G0
- G1
- G2
- G3
- G4
- G5
- G6
- G7
- GND
- R0
- R1
- R2
- R3
- R4
- R5
- R6
- R7
- GND
- DE
- HSYNC
- GND
- VSYNC
- PWR
- DCLK
- GND
- X_L
- X_R
- # LCD Standby Mode PWR: 50uW
- Y_B
- Y_T
- SPI_CLK
- SPI_MOSI
- SPI_MISO
- SPI_CS
- I2C_CLK
- GND
- I2C_SDA
- VDD_1.8V
- VDD_3.3V
- VDD_5V
- VDD_5V
- PWREN
- RESET
sheet 9
- i.MX6UL EVK PWR TREE
- LDO
- VDD_SNVS_IN
- Always ON
- RICHTEK RT9169
- VDD_SNVS_IN
- LDO_ARM_SOC
- VDD_SNVS_CAP
- 3.3V/100mA Iq = 4uA
- 276uA
- LDO_1P1
- NVCC_PLL
- WALL Adapter: 5V/3A
- OVP
- DC/DC BUCK
- VDD_HIGH_IN
- VSYS
- VDD_HIGH_IN
- LDO_2P5
- VDD_HIGH_CAP
- PMIC_ON_REQ
- MPS MP2144
- 5V/3A
- 3.3V/2A Iq=40uA
- DCDC_3V3
- 125mA
- NVCC_GPIO/NVCC_ENET/NVCC_LCDIF
- NVCC_DRAM_2P5
- # MCIMX6UL-BB
- DC/DC BUCK
- VDDARM_IN
- VDD_ARM_CAP
- VDD_SOC_IN
- LDO_ARM_SOC
- DCDC_3V3_PG
- MPS MP2159
- 900mA
- VDD_SOC_CAP
- 1.275V/1A Iq=40uA
- DC/DC BUCK
- VDD_MEM1V5
- NVCC_DRAM
- MPS MP2159
- DCDC_3V3_PG
- 50mA
- FSL i.MX6UL CPU
- 1.35V/1A Iq=40uA
- NVCC_NAND
- # 1.8V for eMMC HS200 mode
- LDO
- RICHTEK RT9169
- 1.8V/100mA Iq = 4uA
- HIGH PSRR LDO
- VLDO_3V3
- RICHTEK RT9193
- VDDA_ADC_3P3
- DCDC_3V3
- 3.3V/300mA
- LDO
- NVCC_SD (3.3V/1.8V)
- RICHTEK RT9065
- NVCC_SD
- DCDC_3V3_PG
- 1.8V/3.3V/500mA
- # 1.8V for CSI;
  1.8V/3.3V for SIM
- LDO
- NVCC_CSI (1.8V/3.3V)
- RICHTEK RT9065
- NVCC_CSI
- DCDC_3V3
- 1.8V/3.3V/500mA
- USB_OTG_VBUS
- 50mA
- USB_OTG1_VBUS
- LOAD SW
- USB_HOST_VBUS
- LDO_USB
- VDD_USB_CAP
- USB_OTGx_PWR
- USB_OTG2_VBUS
- VLCD_3V3
- RGB LCD
- 3.3V/23mA
- TianMa TFT
- 5S2P
- BACKLIGHT
- LvDDR3
- BLT_PWM
- 16V/25mA
- RICHTEK RT9293B
- Micron: MT41K512M16
- VHDMI_3V3
- HDMI
- 3.3V/10mA
- DCDC_3V3
- LDO
- SILICON IMAGE SiI9022A
- VLDO_1V2
- 3.3V/200mA
- eMMC 4GB
- 1.2V/69.2mA
- RICHTEK RT9169
- Micron MTFC8GLCDM
- VSPK_5V
- NVCC_NAND
- 5V/511mA
- 3.3V/1.8V
- Audio Codec
- DVDD_1V8
- LDO
- Wolfson WM8962B
- VAUD_3V3
- UM1750S-00
- DCDC_3V3
- QSPI
- 3.3V/62.58mA
- 3.3V/20mA
- Micron N25Q256
- SENSOR
- VSENSOR_3V3
- eCompass/
  G-sensor/Gyroscope
- 3.3V/6.9mA
- DCDC_3V3
- NAND
- # MCIMX6UL-CM
- 3.3V/50mA
- Micron MT29F32G08
- CAN_VIO_3V3
- CAN
- 3.3V/1mA
- NXP  TJA1044GT/3
- CAN_VDD_5V
- 5V/65mA
- USB_OTG_VBUS
- USB OTG
- Ethernet x2
- VENET_3V3
- 3.3V/48.7mA
- LOAD SW
- USB_HOST_VBUS
- Micrel KSZ8081RNB
- USB HOST
- AVDD_2V8
- LDO
- RICHTEK RT9065
- SD Socket
- 2.8V/500mA
- LOAD SW
- SD1_nRST/POR_B
- Camera/EMV SIM
- CSI B2B CN
- LDO
- DVDD1V5
- BT MOD
- RICHTEK RT9065
- 1.5V/500mA
sheet 10
- i.MX6UL EVK Block Diagram
- #####  Blcok Diagram Rev 1.0  #####
- # MCIMX6UL-BB
- EMV SIM Socket
- MPN: MCIMX6UL-BB
  MPN: MCIMX6UL-CM
- Agile No: 28616
  Agile No: 28617
- smart card
- HDMI
- LCD
- Camera
- CAN x2
- JTAG
- Micro USB
- USB HOST
- 4.3" TFT 480x272
- Silicon Image
     SiI9022A
- OV5642 5MP
- NXP TJA1044GT/3
- PIN Header
- DISP
- CSI/SIM
- USB OTG1
- USB OTG2
- CAN x2
- JTAG
- SODIMM
- # MCIMX6UL-CM
- NAND
- PWR
- eMMC/MicroSD
- POWER
- eMMC 4.51 Footprint only
- Discrete PWR
- NAND/SDIO/QSPI
- NAND/SD2/QSPIA
- QSPI
- FREESCALE
     i.MX6UL
- Micron N25Q256A
- DDR3/LvDDR3
- x16 bits
- DRAM
- Micron 8Gb: MT41K512M16
- SODIMM
- UART
- I2C/INT
- SD1
- RMII x2
- I2S
- UART
- Motion Sensors
- BlueTooth
- SD SLOT
- Ethernet x2 (RMII)
- CODEC
- UART-USB bridge
- eCompass MAG3110FCR2
- Full Size
- Silabs CP2102
- FPC Module
- Accelerometer FXLS8974CFR3
- 100Base-TMicrel KSZ8081
- Wolfson WM8962B
- Gyroscope: FXAS21000CQR1
- HP
- MIC
sheet 11
- MCIMX6UL-BB
- Schematics DevBoard
- Table of Content
- Revision History
- Page 1
- Cover
- Rev. Code
- Date
- By
- Description
- Page 2
- Block Diagram
- A
- 2015-02-28
- Javen
- 1
- Revision A released
- Page 3
- PWR TREE
- Page 4
- LCD
- Page 5
- HDMI
- B
- 2015-07-07
- Javen
- 1
- DNP R1023
- DNP R1435, R1404, Add R1436
- Page 6
- USB
- DNP R1517,Install R1520
- Change Camera J1801 connector
- Page 7
- CAN
- Change JTAG J1902 footprint
- Change SODIMM J2101 footprint
- Page 8
- Sensor
- Change R2101 from PU to PD
- Change J1901 PIN sequence
- Page 9
- Codec
- Page 10
- Ethernet x1
- C
- 2015-07-14
- Javen
- 1
- Add R919-R946,L903-L905
- Page 11
- Ethernet x2
- DNP R1436,Install R1404,R1435
- Change HP_MIC1N to LINPUT1
- Page 12
- SD/BT
- Add BT_DISABLE,ECSPI4_SS0,ECSPI4_MOSI,ECSPI4_SCLK for BT
- Add R2107~R2116 to reduce the VSNVS power consumption due to the TAMPER reason
  Add L903~L930 as FCC/CE backup
- Page 13
- Camera
- Change Camera J1801 connector direction on layout
- Page 14
- DBG/JTAG
- Add C905
- Page 15
- SYS PWR
- Change J1701 from TOP contact to BOT contact for BT
- Page 16
- SODIMM BB
- Page 17
- NOTE
- Page 18
- IOMUX
- C1
- 2016-05-05
- Javen
- 1
- DNP J1801,J1001 due to cost reason
- Page 19
- Page 20
- Page 21
- Updated to be NCL compliance.
  - parts: J901, J1701, J1802, J2101
  - Title blocks
- C2
- 18-Oct-2016
- Marek B.
- Page 22
- Page 23
- C3
- 17-May-2018
- Marek B.
- U1302 set to DNP (Obsolete)
  U1201 & U1202 changed to TJA1044GT/3
- Page 24
- 1. U1401 is updated to WM8962BECSN/R
  2. D1903 is updated to APB3025ESGC-F01.
  3. J1001 is updated to HD119F-3A04205
  4. U1301 is updated to FXLS8974CFR3
  5. U2106 (UM1750S-00) is added for generating DVDD_1V8
- D
- 14-Sept-2022
- Annanya
  Gupta
- Page 25
- Page 26
- 1. R1807, R1808, R1810, R1811 value updated to 1.2K
  2. R1407, R1431, R1432, R1433, R1434 value updated to 51 Ohms
  3. Updated the block diagram & Power tree
  4. Added I2C redriver U2107(TCA9416DDFR) for I2C2 port near Audio Codec
  5. Added R2141, R2142, R2143, R2144, R2145, R2146, R2147, C2161
  6. Made DNP - R2141, R2142, R2143, R2144, R2146, R2147
  7. Added R2148
- Page 26
- E
- 17-April-2023
- Bhaskar
  Reddy N
- Page 27
- Page 28
- 3. Device type number is for reference only. The number
      varies with the manufacturer.
- 1. Unless Otherwise Specified:
- All resistors are in ohms, 10%, 1/8 Watt,0603
- 4. Special signal usage:
- All capacitors are in uF, 20%, 50V,0603
- _B Denotes - Active-Low Signal
- All voltages are DC
- <> or [] Denotes - Vectored Signals
- All polarized capacitors are aluminum electrolytic
- 5. Interpret diagram in accordance with American
  National Standards Institute specifications, current
  revision, with the exception of logic block symbology.
- 2. Interrupted lines coded with the same letter or letter
      combinations are electrically connected.
